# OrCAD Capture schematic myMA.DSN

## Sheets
1 - Cover Page: title: COVER PAGE; rev: 01; note: DE-002031
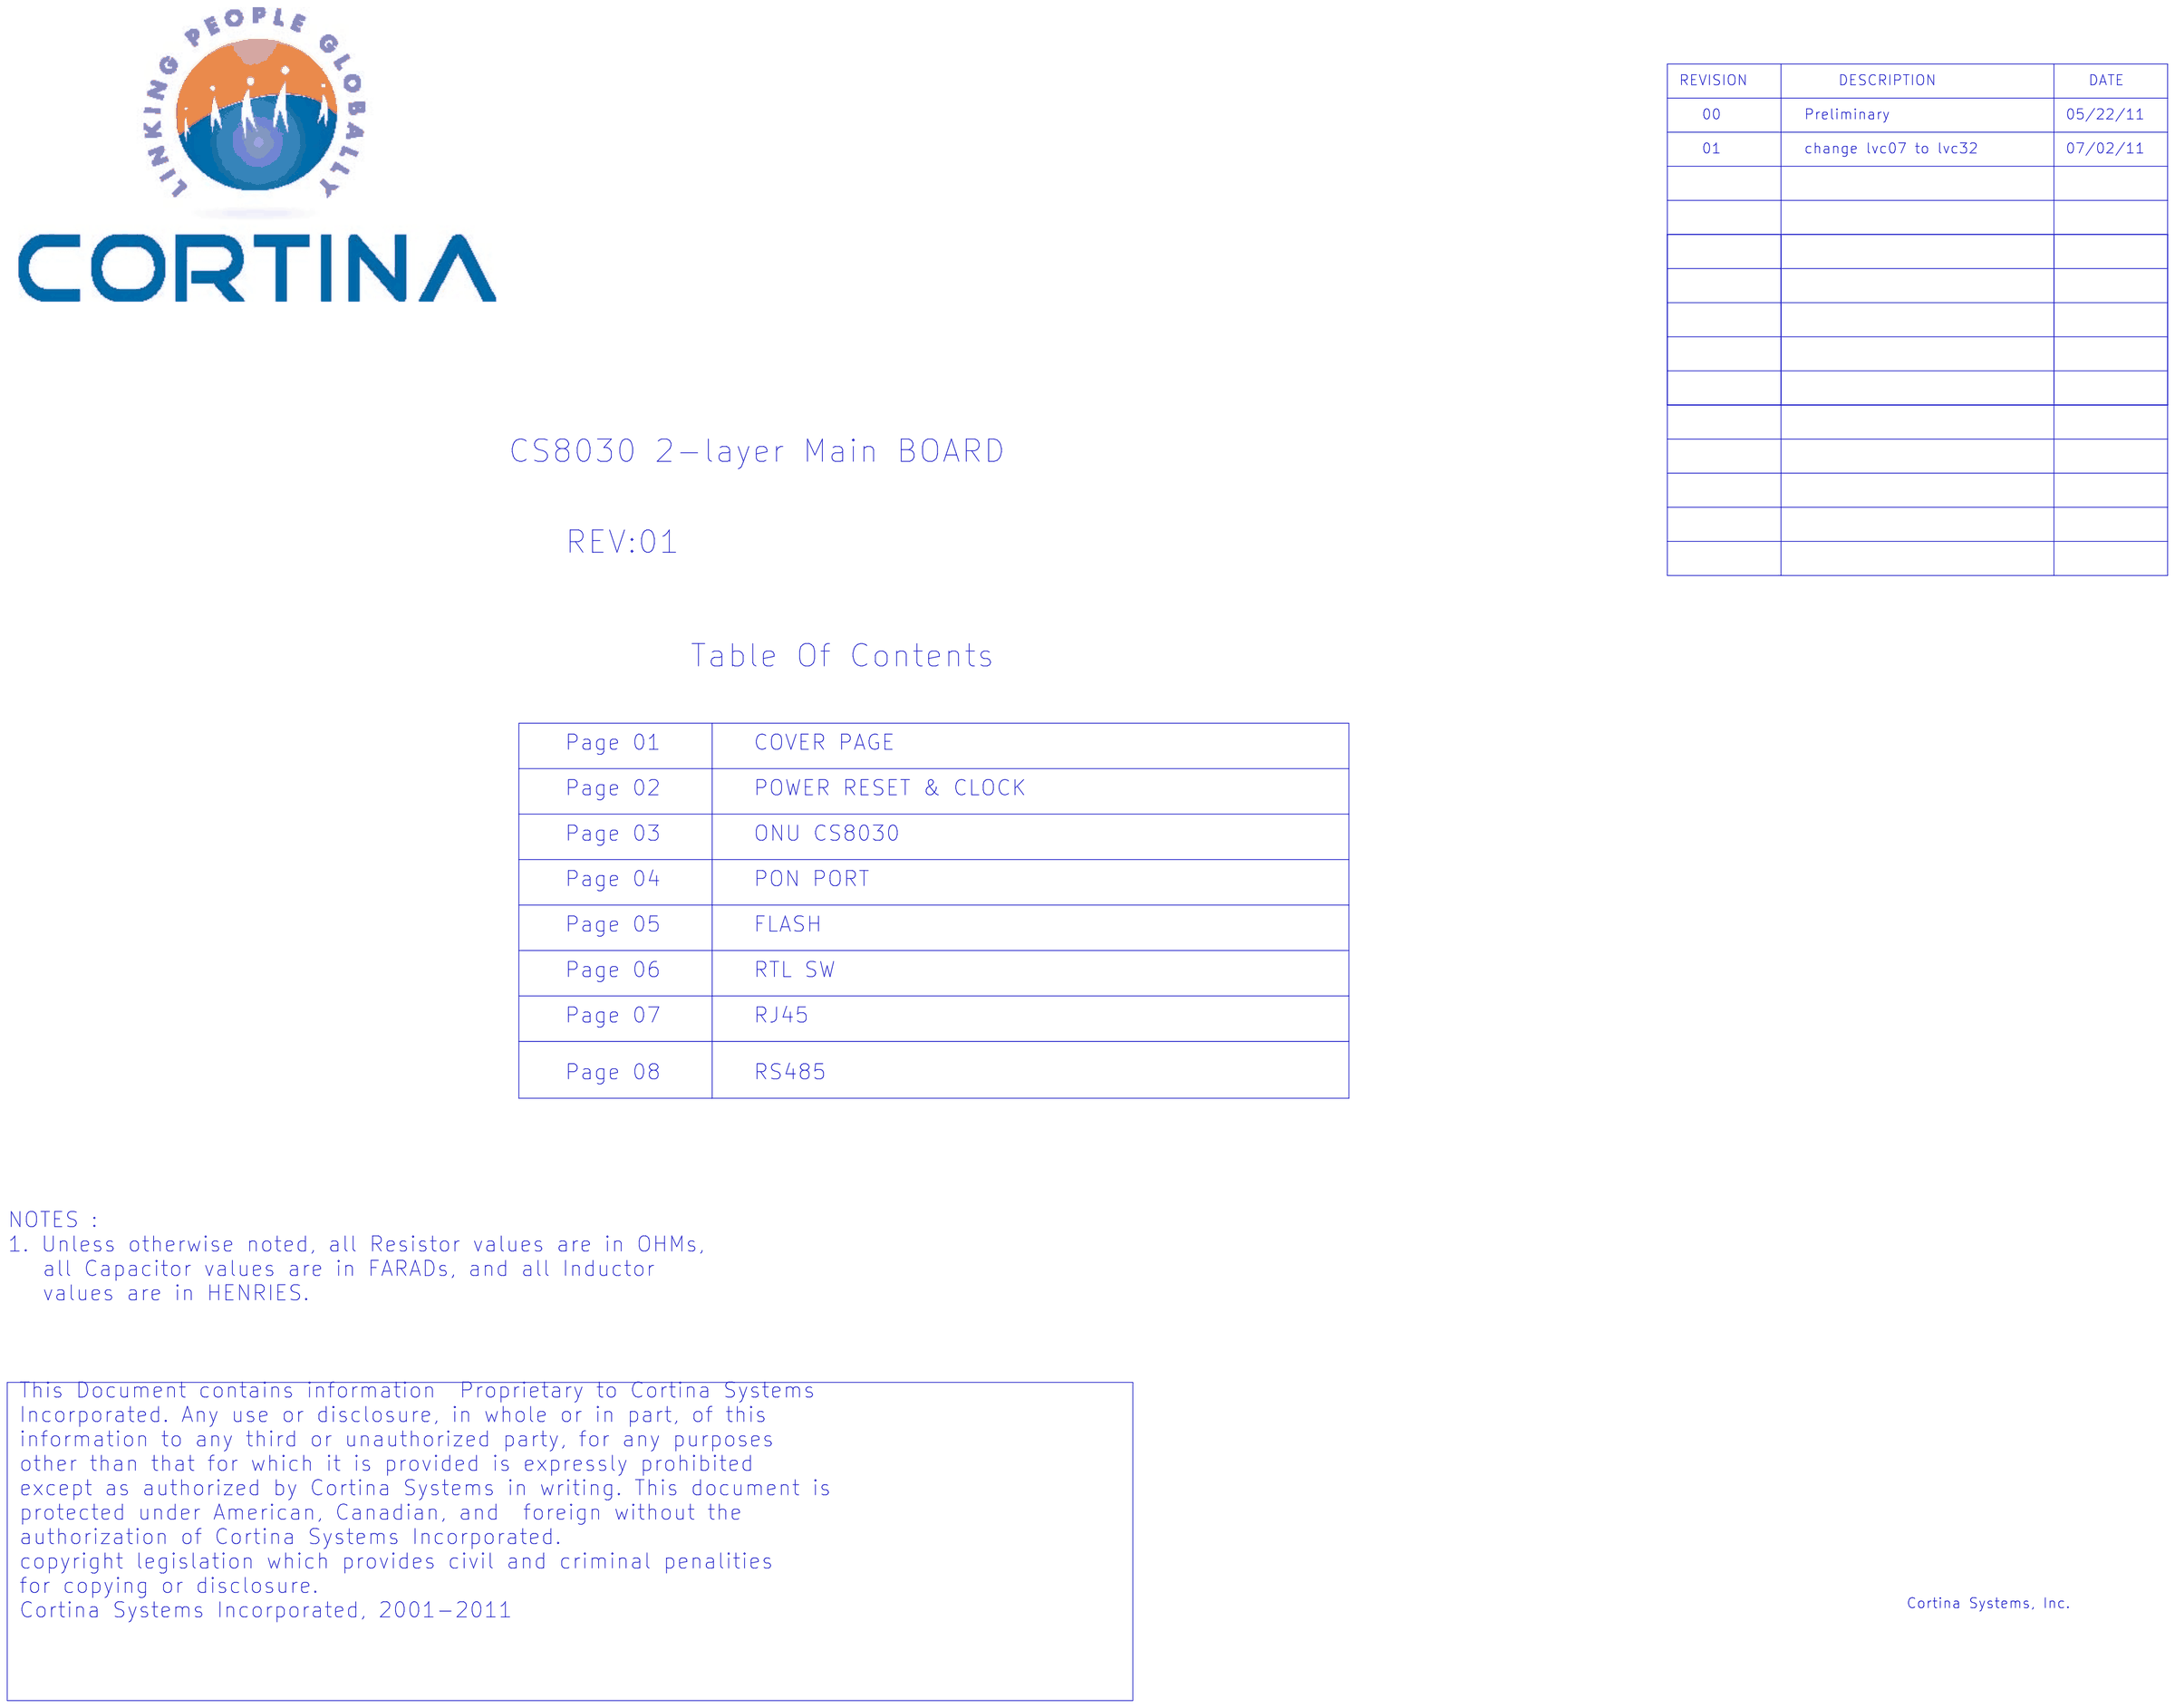
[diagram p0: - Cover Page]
2 - POWER RESET&CLOCK: size C; title: POWER RESET&CLOCK
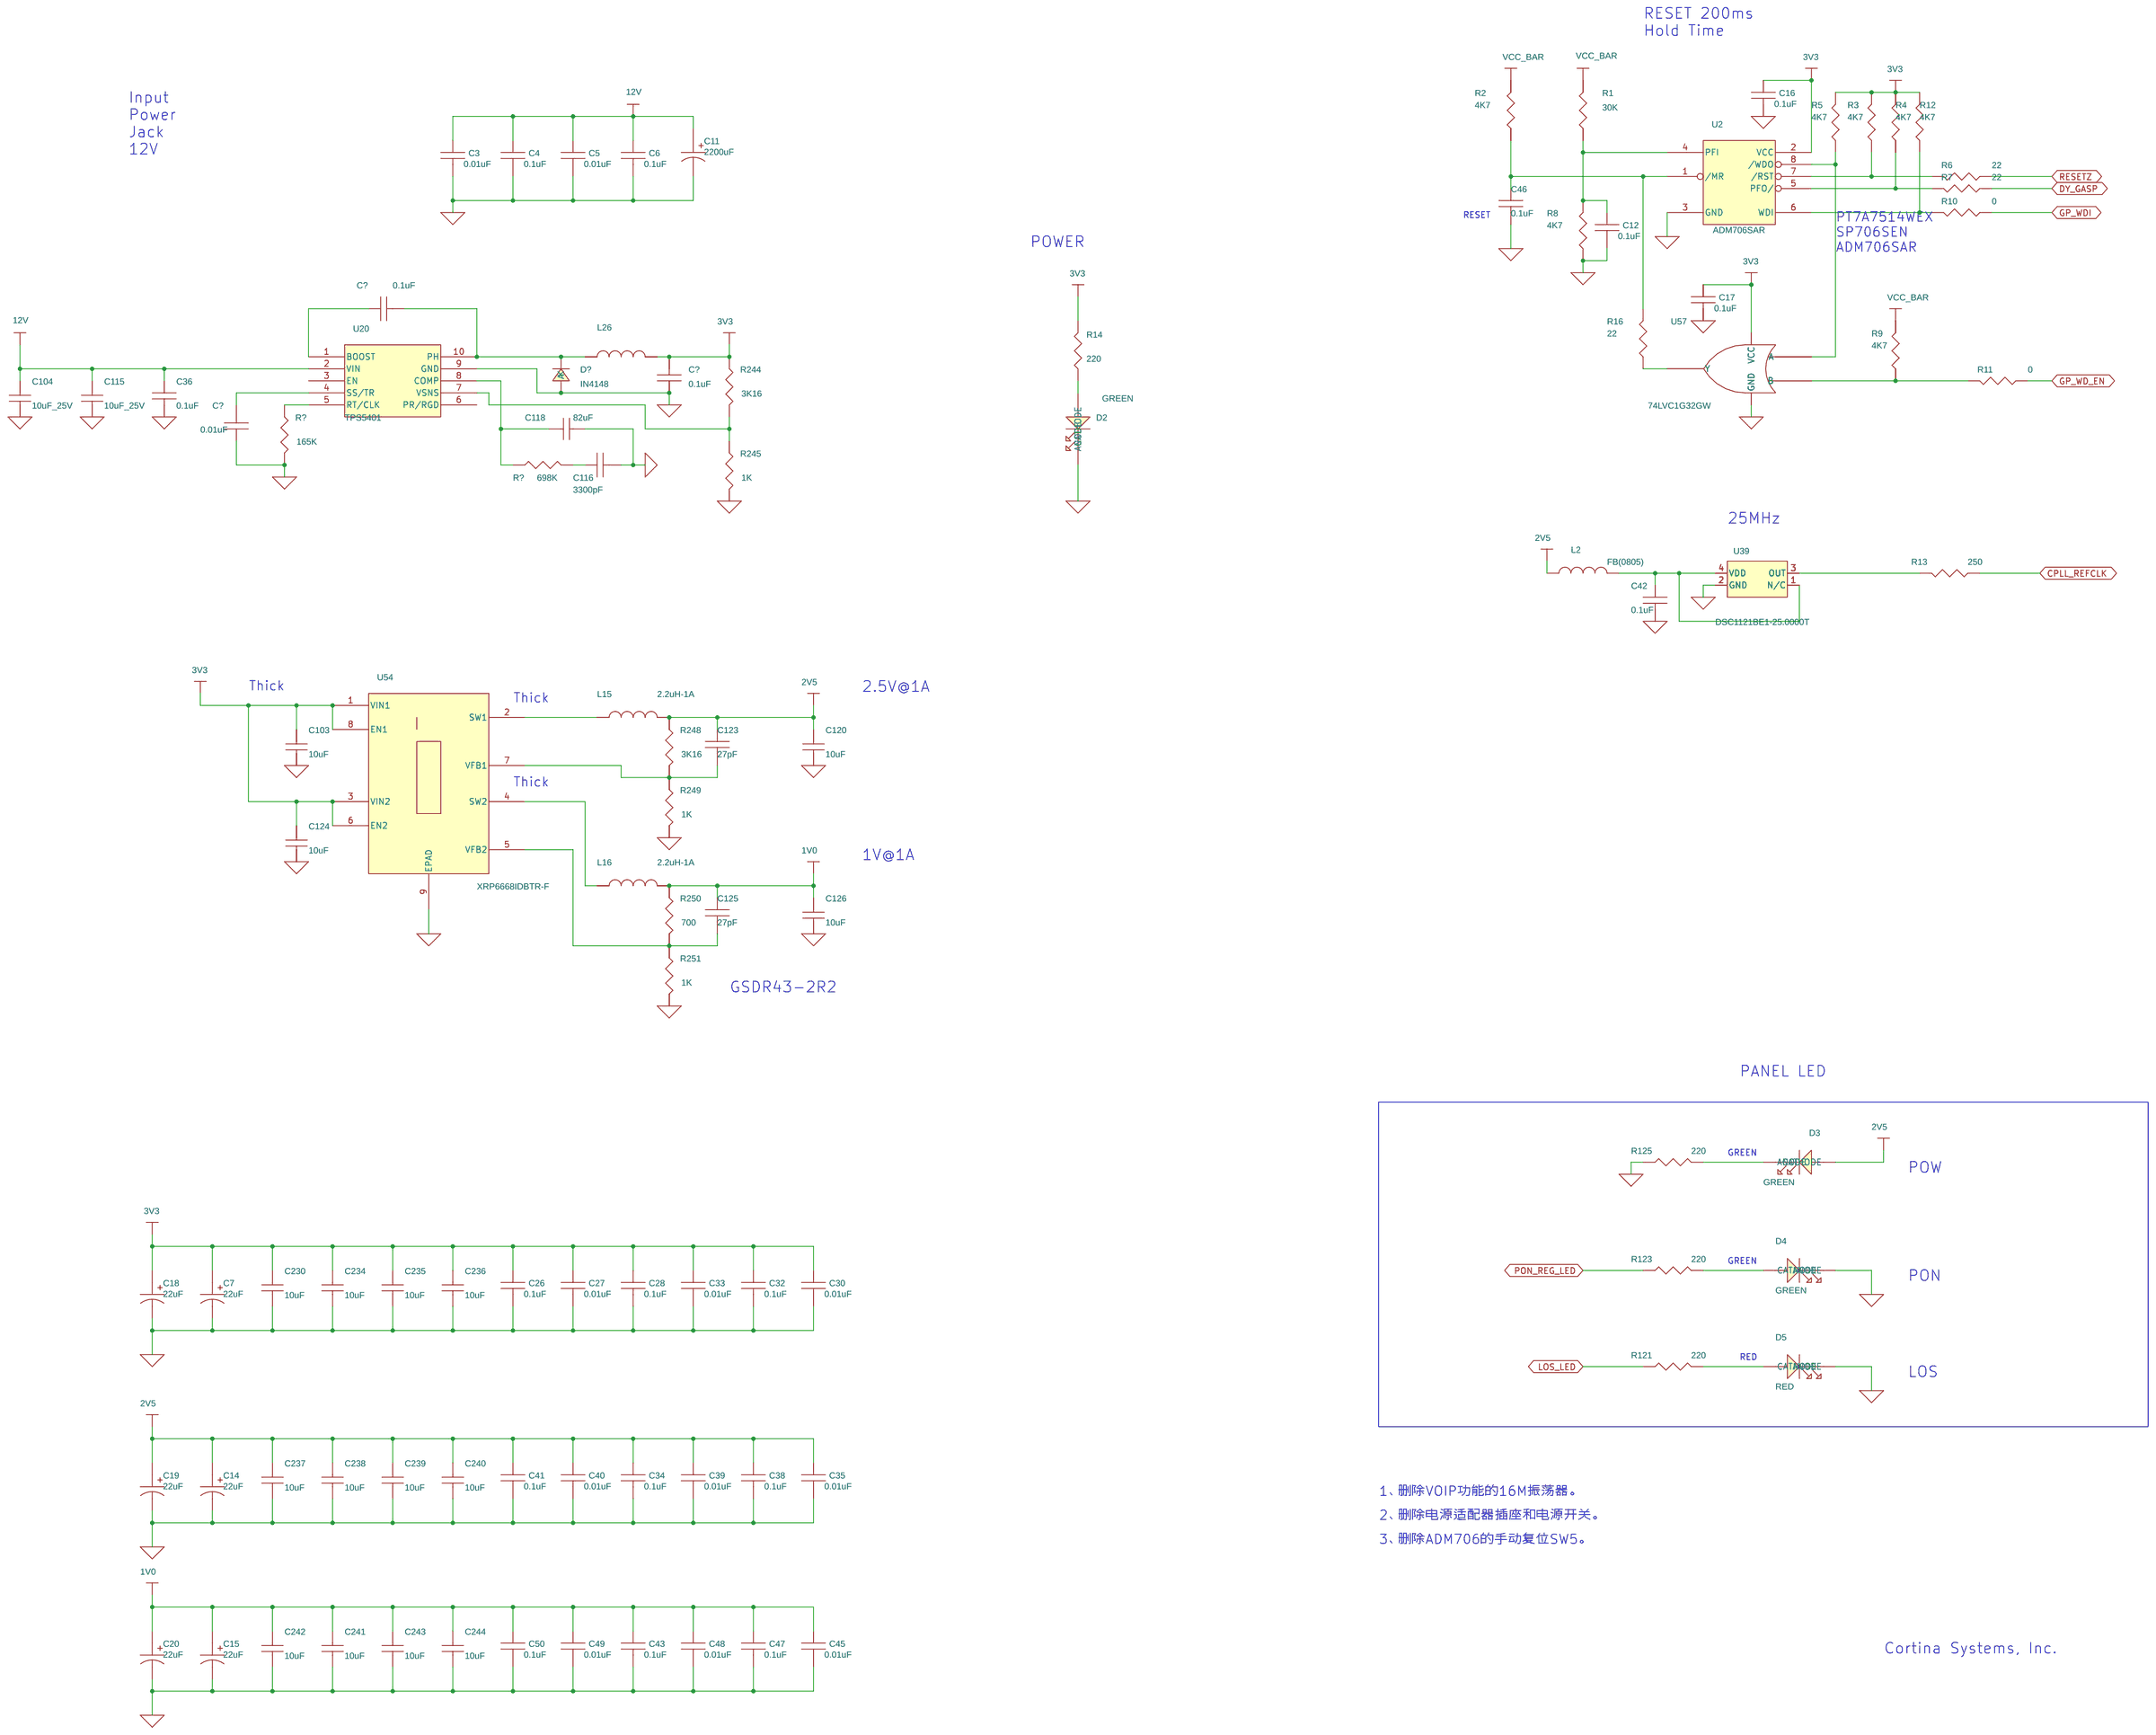
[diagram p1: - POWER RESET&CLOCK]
3 - ONU CS8030: size C; title: CS8030
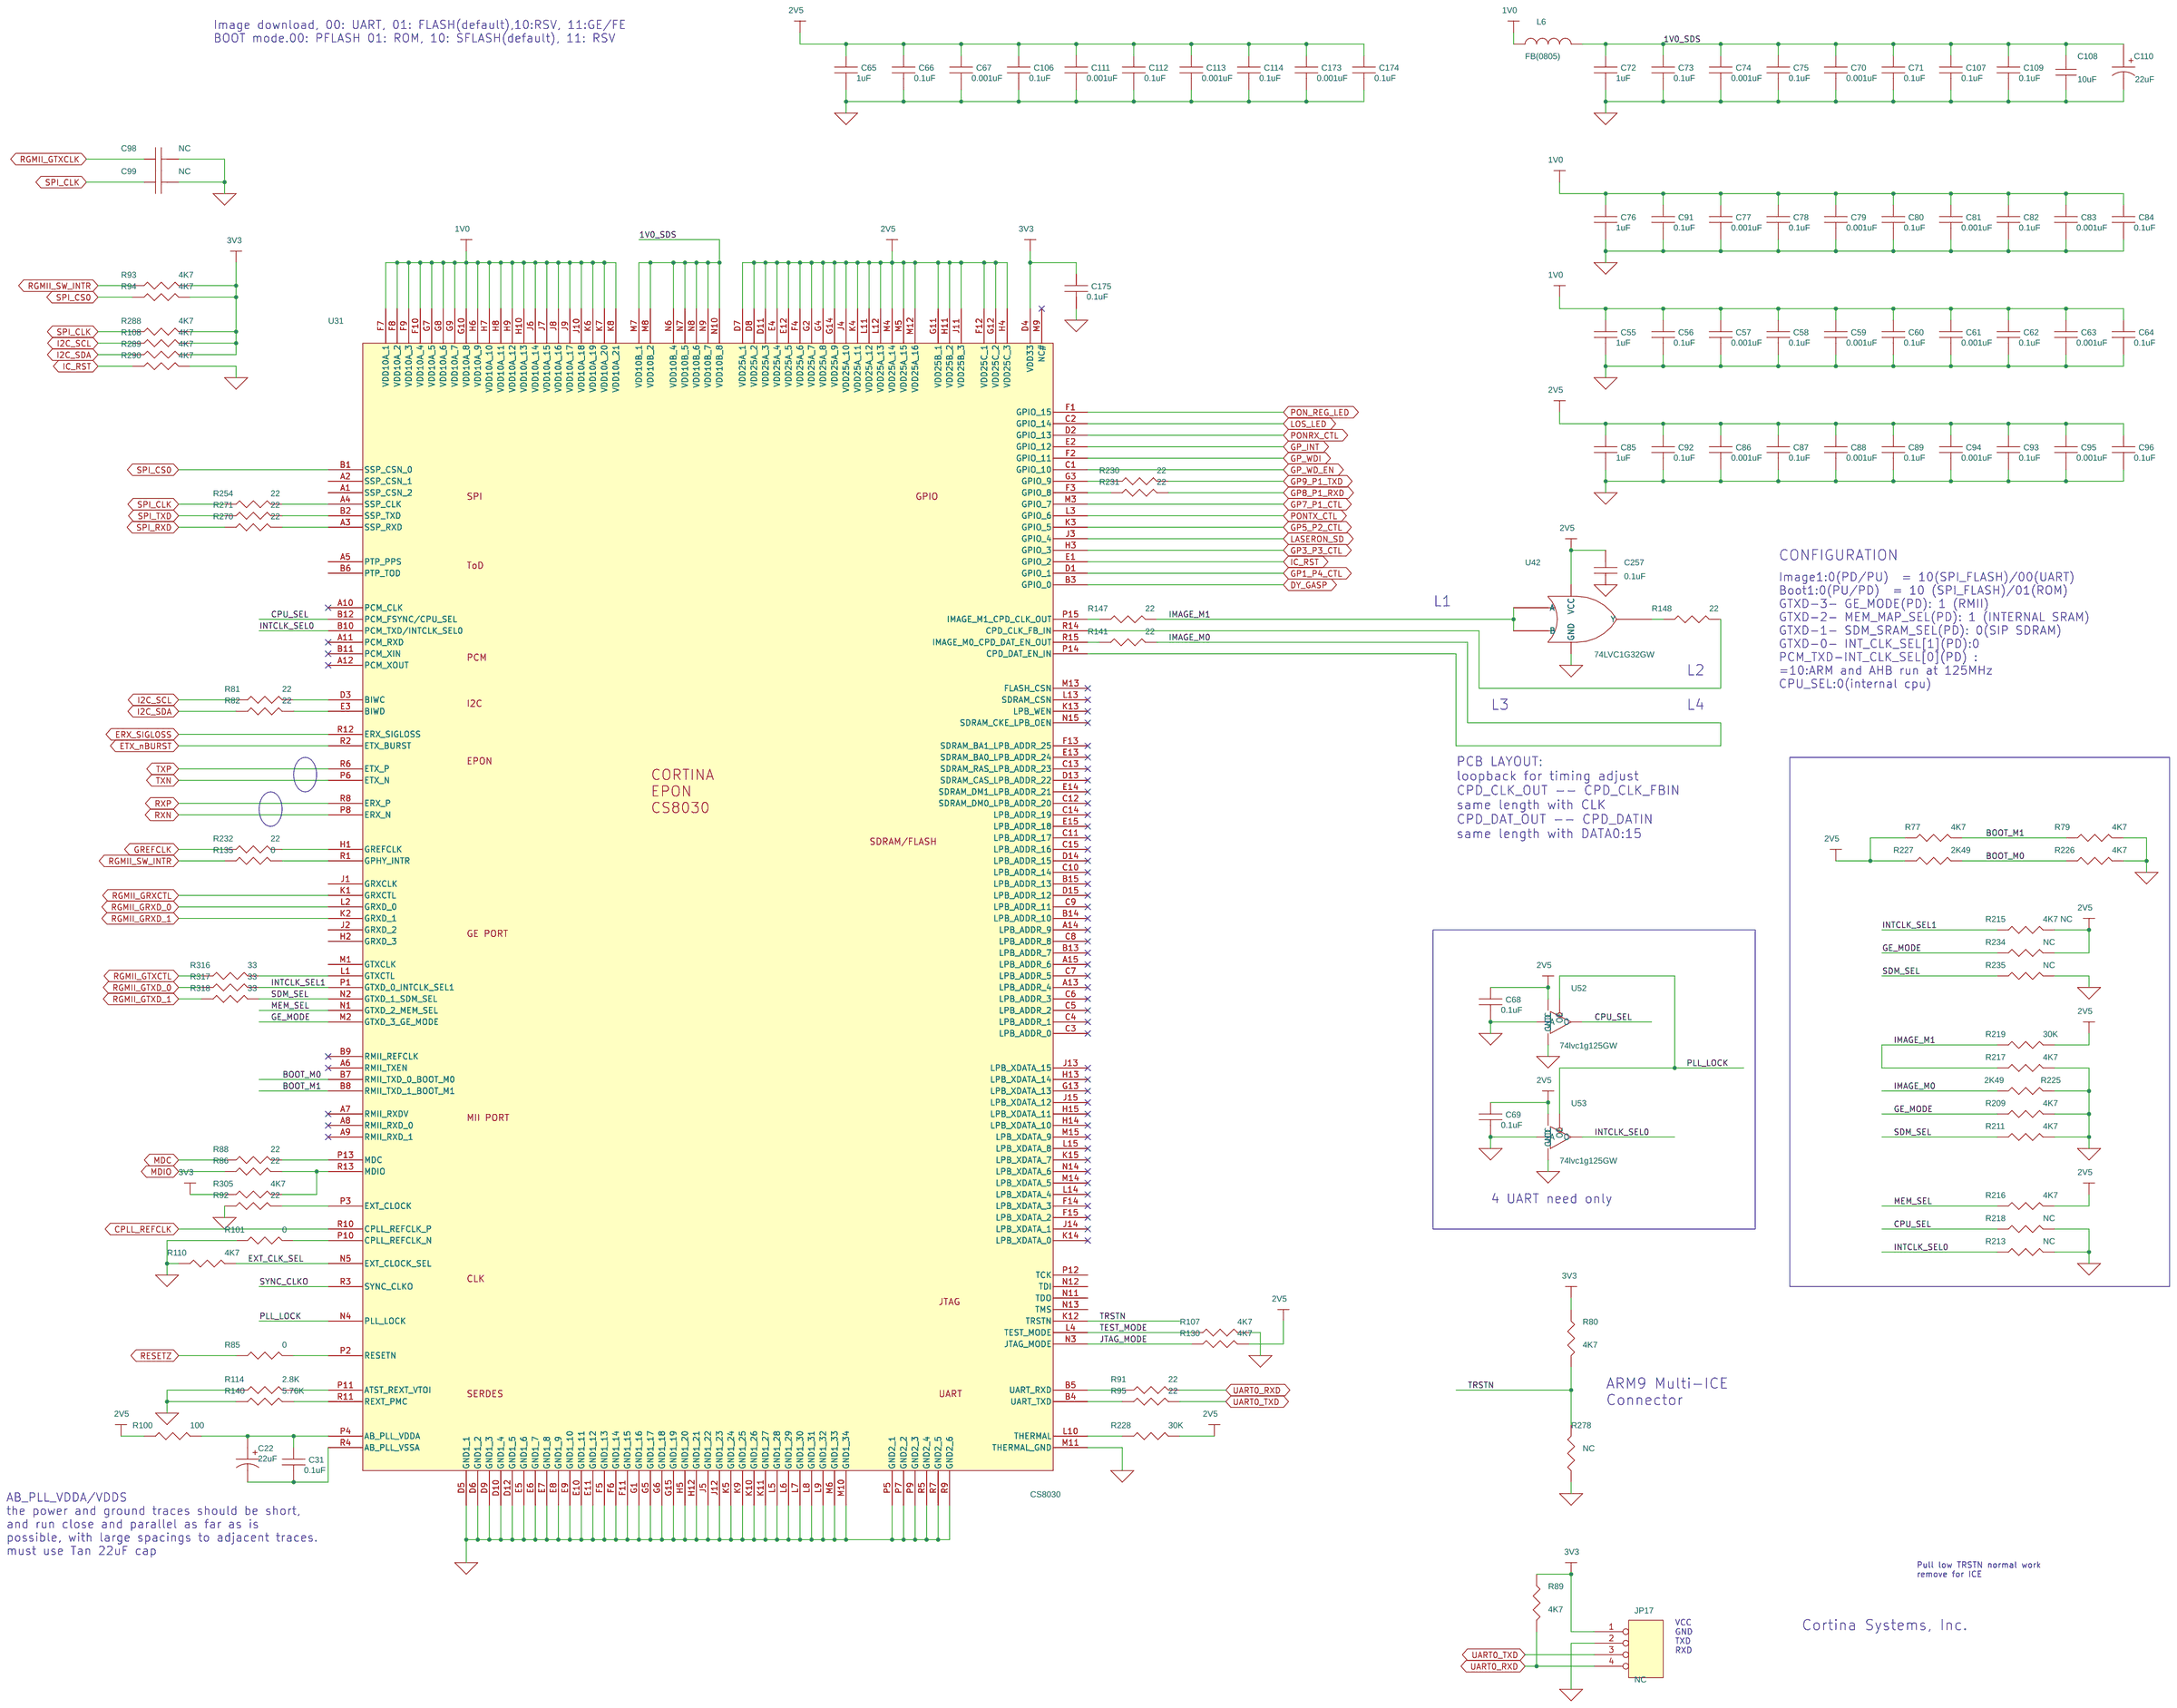
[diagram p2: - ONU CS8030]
4 - PON PORT: size C; title: PON PORT
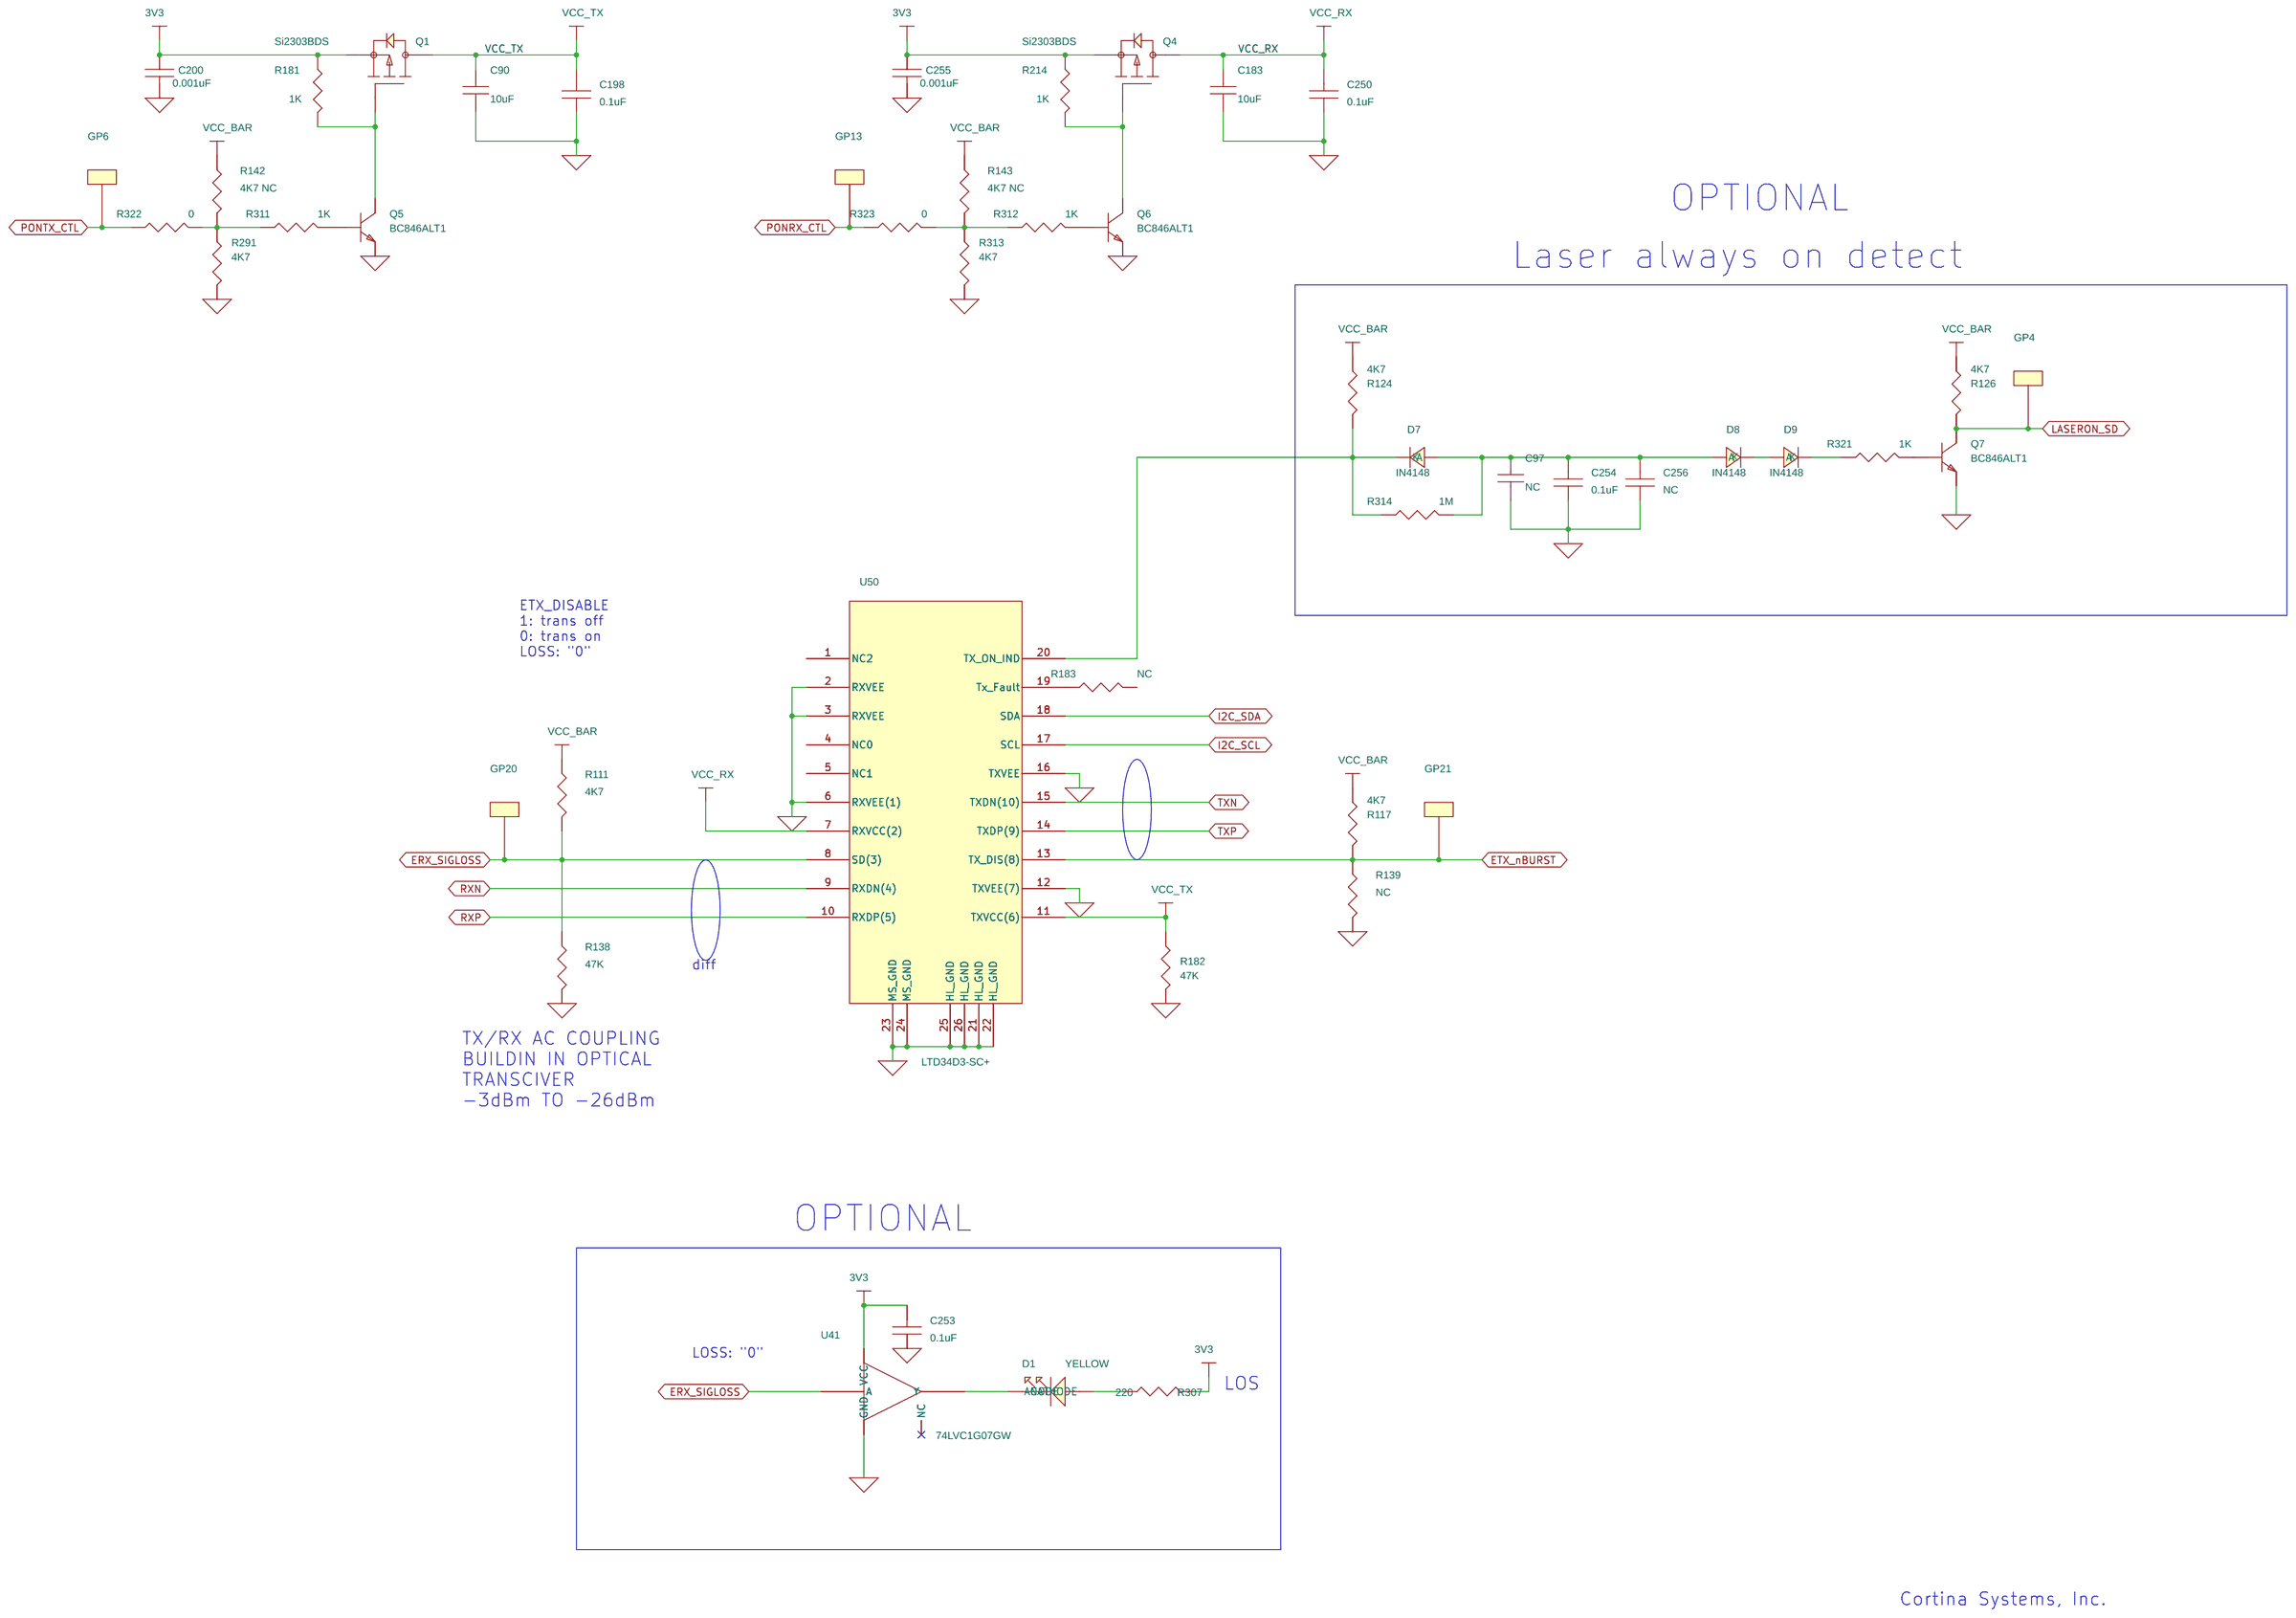
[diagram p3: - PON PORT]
5 - SFLASH_SDRAM: size C; title: FLASH
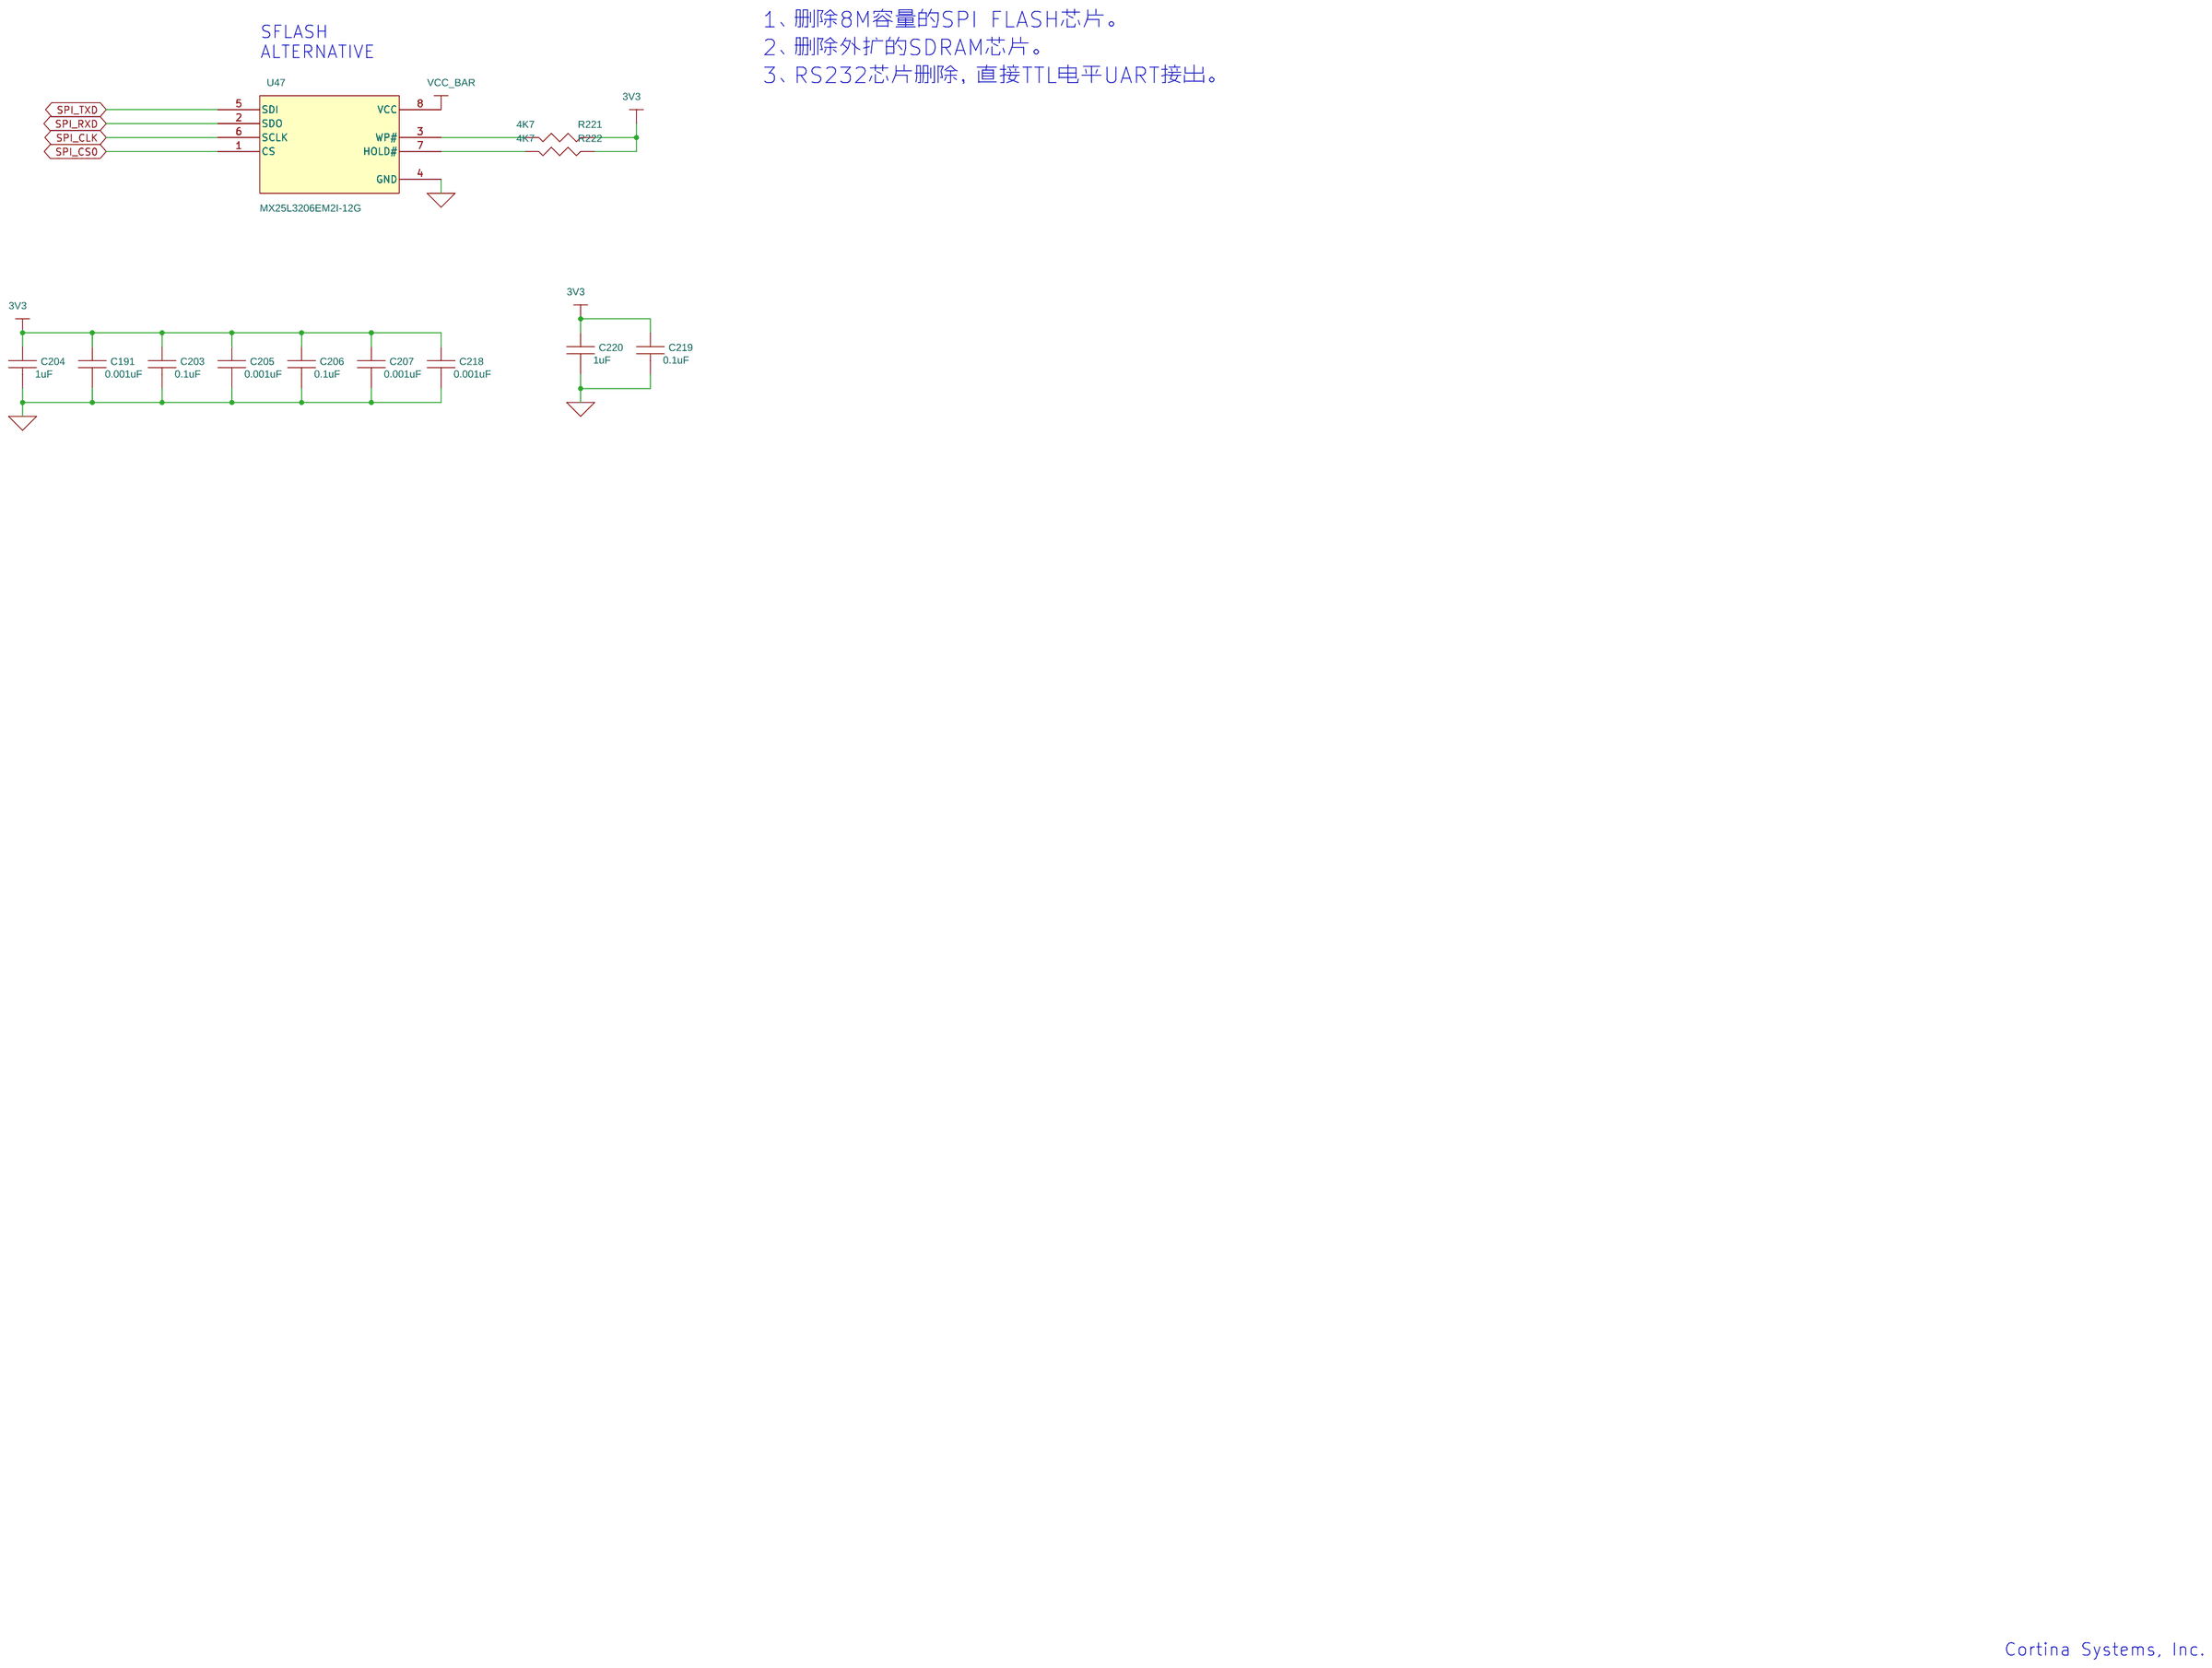
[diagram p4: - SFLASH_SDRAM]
6 - SW_PHY_IF: size C; title: SW PHY
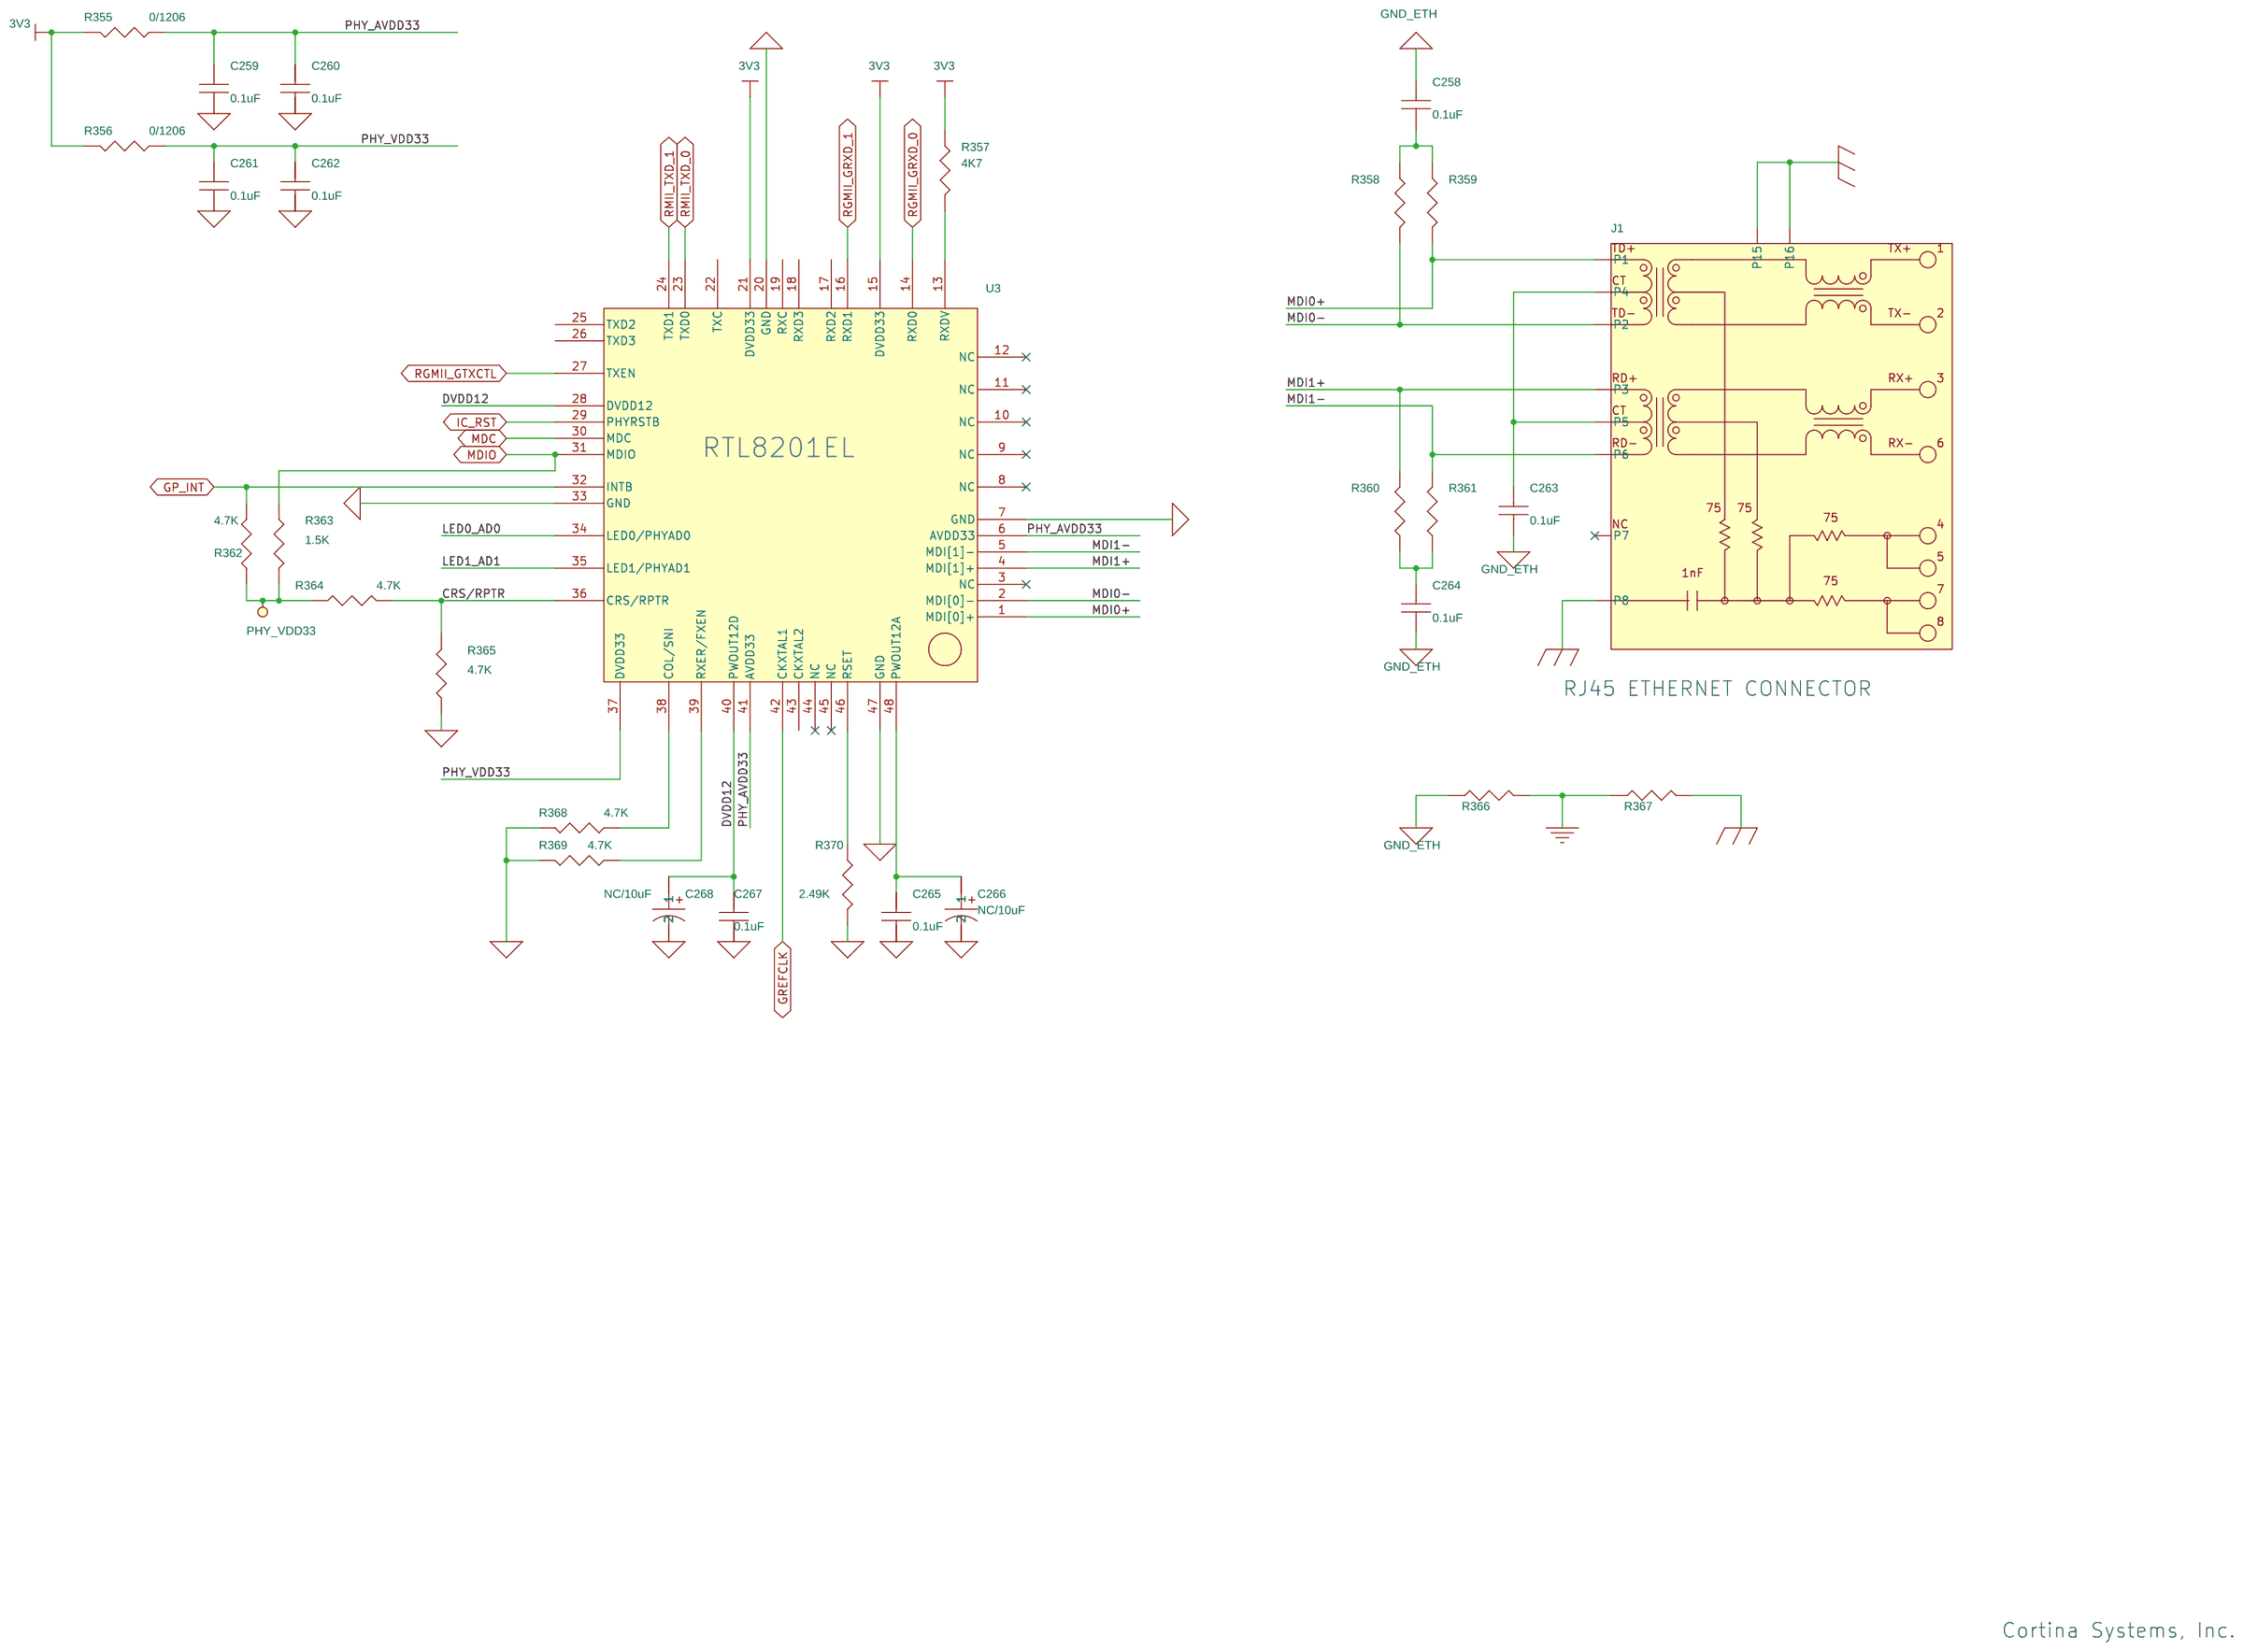
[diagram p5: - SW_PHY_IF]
7 - SLIC_IF: title: SLIC
8 - RS485_RS232: size C; title: RS485
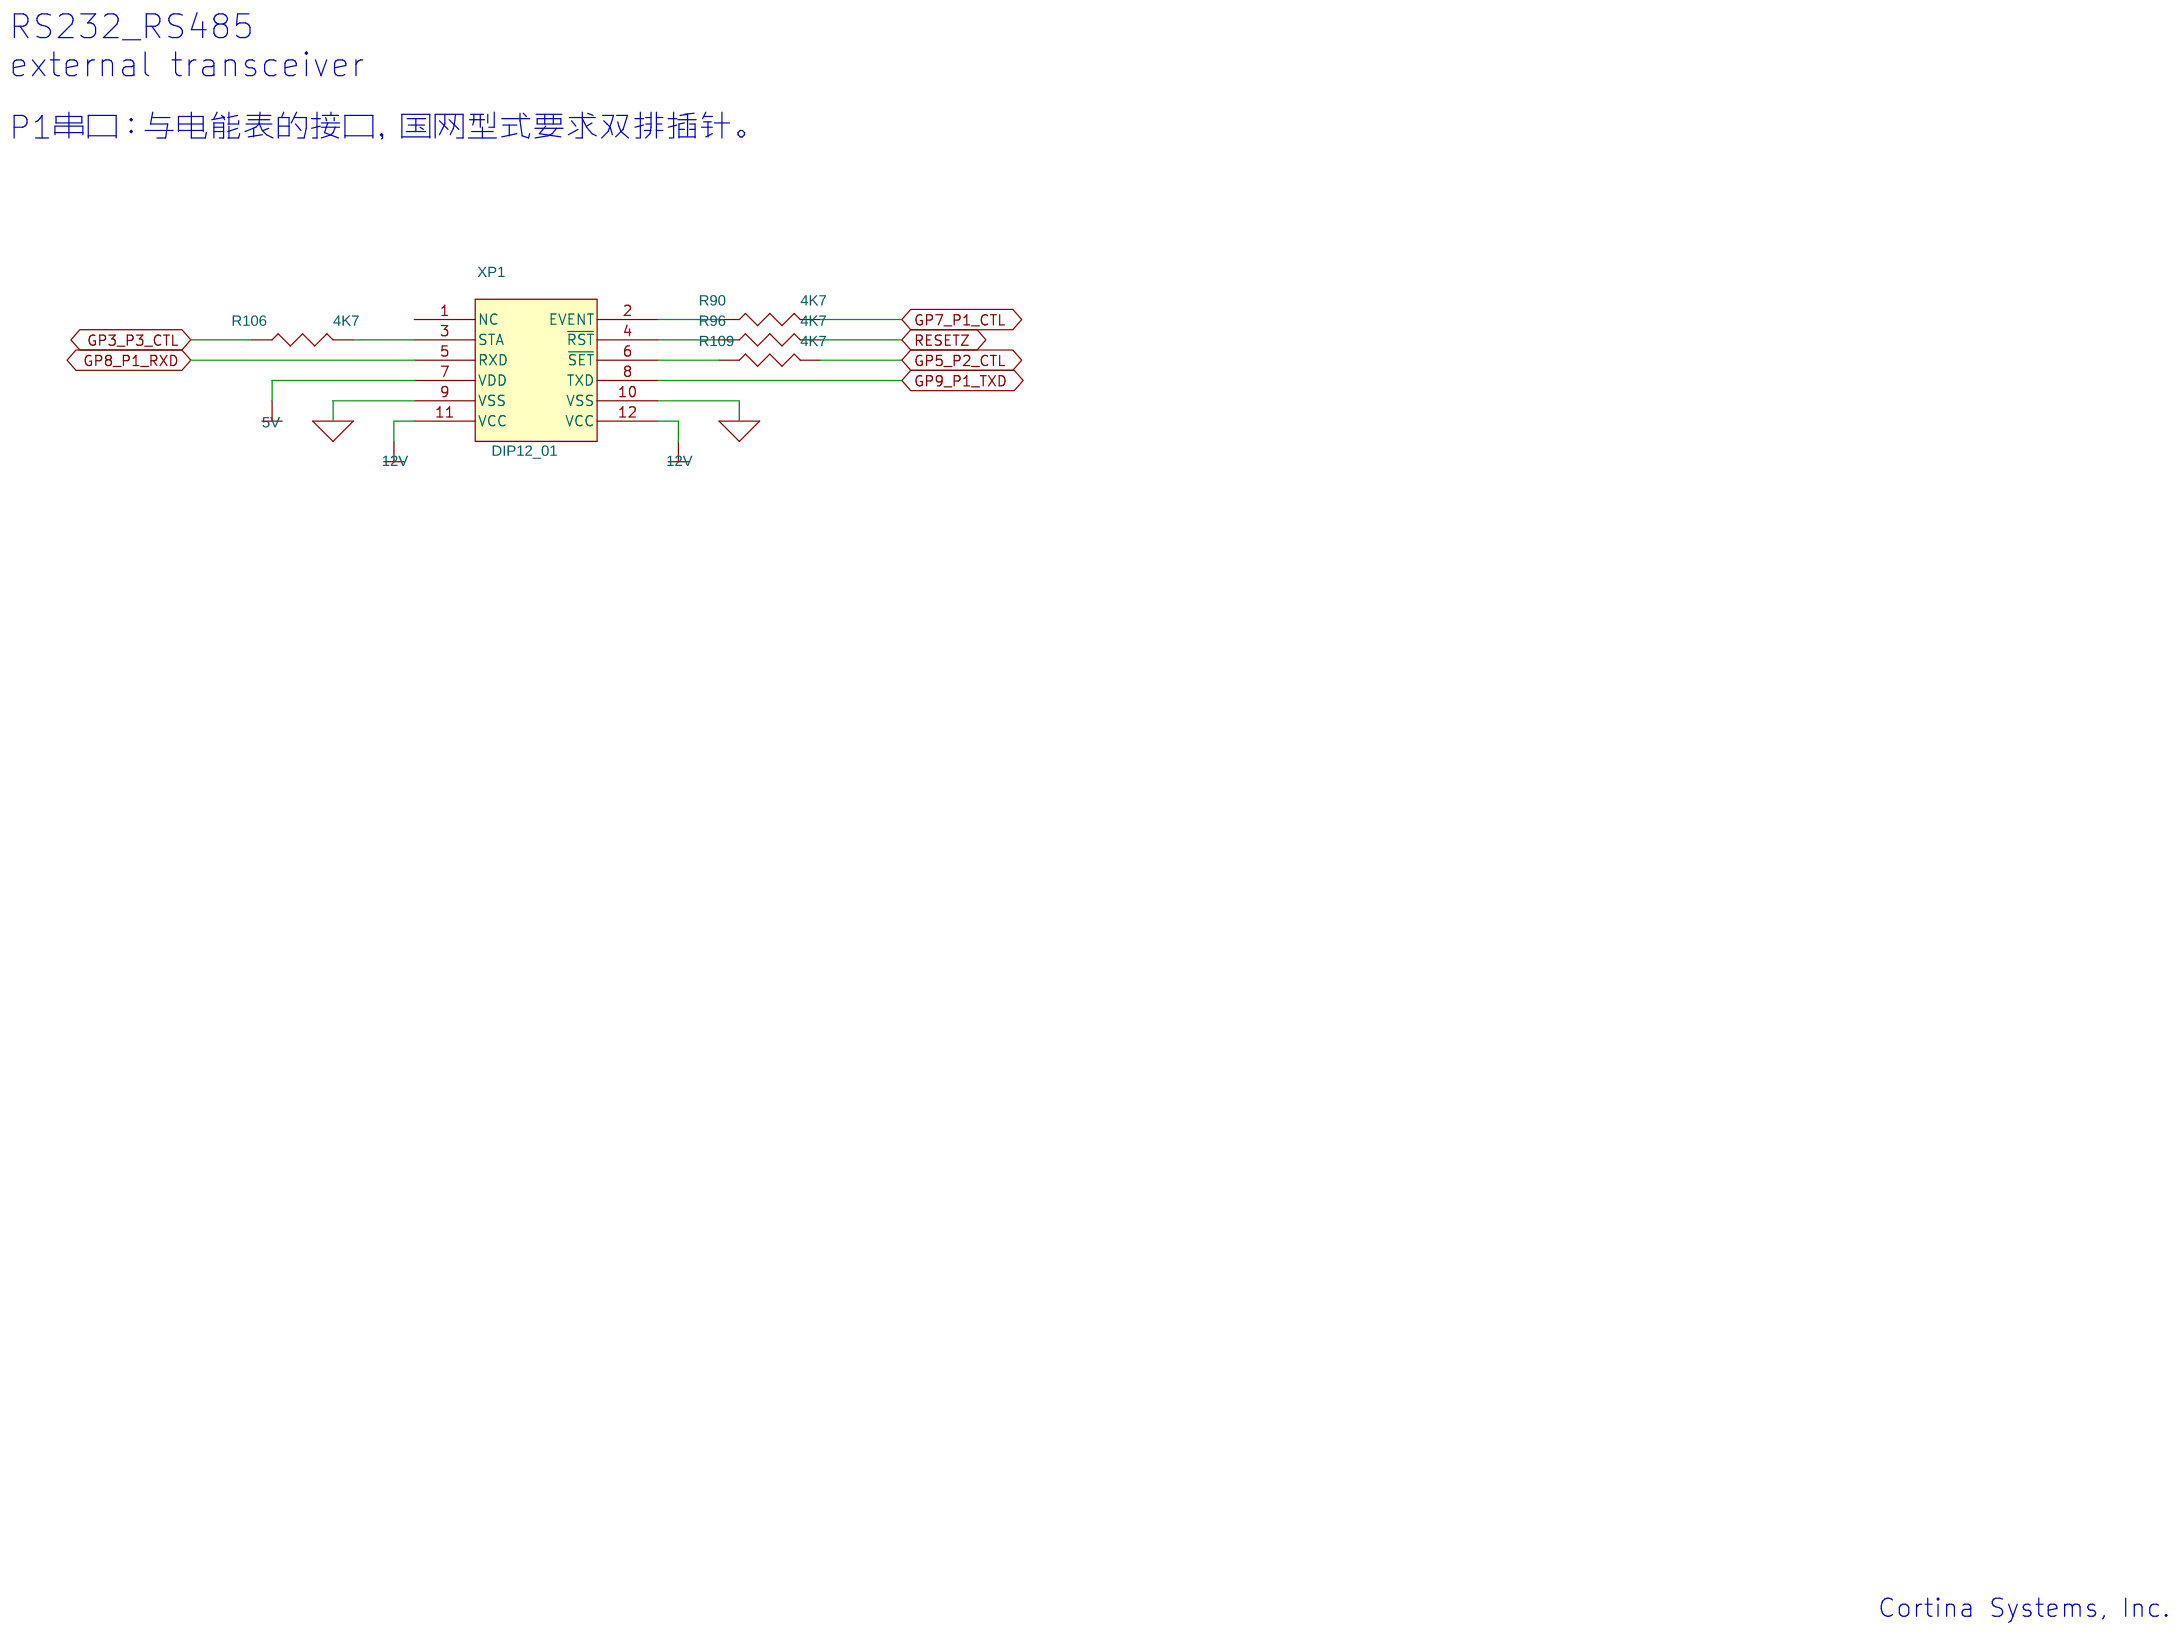
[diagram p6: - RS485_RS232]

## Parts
sheet - ONU CS8030
C22  22uF  [STC3216]
C31  0.1uF  [SC0402]
C55  1uF  [SC0402]
C56  0.1uF  [SC0402]
C57  0.001uF  [SC0402]
C58  0.1uF  [SC0402]
C59  0.001uF  [SC0402]
C60  0.1uF  [SC0402]
C61  0.001uF  [SC0402]
C62  0.1uF  [SC0402]
C63  0.001uF  [SC0402]
C64  0.1uF  [SC0402]
C65  1uF  [SC0402]
C66  0.1uF  [SC0402]
C67  0.001uF  [SC0402]
C68  0.1uF  [SC0402]
C69  0.1uF  [SC0402]
C70  0.001uF  [SC0402]
C71  0.1uF  [SC0402]
C72  1uF  [SC0402]
C73  0.1uF  [SC0402]
C74  0.001uF  [SC0402]
C75  0.1uF  [SC0402]
C76  1uF  [SC0402]
C77  0.001uF  [SC0402]
C78  0.1uF  [SC0402]
C79  0.001uF  [SC0402]
C80  0.1uF  [SC0402]
C81  0.001uF  [SC0402]
C82  0.1uF  [SC0402]
C83  0.001uF  [SC0402]
C84  0.1uF  [SC0402]
C85  1uF  [SC0402]
C86  0.001uF  [SC0402]
C87  0.1uF  [SC0402]
C88  0.001uF  [SC0402]
C89  0.1uF  [SC0402]
C91  0.1uF  [SC0402]
C92  0.1uF  [SC0402]
C93  0.1uF  [SC0402]
C94  0.001uF  [SC0402]
C95  0.001uF  [SC0402]
C96  0.1uF  [SC0402]
C98  NC  [SC0402]
C99  NC  [SC0402]
C106  0.1uF  [SC0402]
C107  0.1uF  [SC0402]
C108  10uF  [SC0805]
C109  0.1uF  [SC0402]
C110  22uF  [STC3216]
C111  0.001uF  [SC0402]
C112  0.1uF  [SC0402]
C113  0.001uF  [SC0402]
C114  0.1uF  [SC0402]
C173  0.001uF  [SC0402]
C174  0.1uF  [SC0402]
C175  0.1uF  [SC0402]
C257  0.1uF  [SC0402]
JP17  NC  [HEADER4-100]
L6  FB(0805)  [SL0805]
R77  4K7  [SR0402]
R79  4K7  [SR0402]
R80  4K7  [SR0402]
R81  22  [SR0402]
R82  22  [SR0402]
R85  0  [SR0402]
R86  22  [SR0402]
R88  22  [SR0402]
R89  4K7  [SR0402]
R91  22  [SR0402]
R92  22  [SR0402]
R93  4K7  [SR0402]
R94  4K7  [SR0402]
R95  22  [SR0402]
R100  100  [SR0603]
R101  0  [SR0402]
R107  4K7  [SR0402]
R108  4K7  [SR0402]
R110  4K7  [SR0402]
R114  2.8K  [SR0402]
R130  4K7  [SR0402]
R135  0  [SR0402]
R140  5.76K  [SR0402]
R141  22  [SR0402]
R147  22  [SR0402]
R148  22  [SR0402]
R209  4K7  [SR0402]
R211  4K7  [SR0402]
R213  NC  [SR0402]
R215  4K7 NC  [SR0402]
R216  4K7  [SR0402]
R217  4K7  [SR0402]
R218  NC  [SR0402]
R219  30K  [SR0402]
R225  2K49  [SR0402]
R226  4K7  [SR0402]
R227  2K49  [SR0402]
R228  30K  [SR0402]
R230  22  [SR0402]
R231  22  [SR0402]
R232  22  [SR0402]
R234  NC  [SR0402]
R235  NC  [SR0402]
R254  22  [SR0402]
R270  22  [SR0402]
R271  22  [SR0402]
R278  NC  [SR0402]
R288  4K7  [SR0402]
R289  4K7  [SR0402]
R290  4K7  [SR0402]
R305  4K7  [SR0402]
R316  33  [SR0402]
R317  33  [SR0402]
R318  33  [SR0402]
U31  CS8030  [BGA_08_225]
U42  74LVC1G32GW  [SOT353]
U52  74lvc1g125GW  [SOT353]
U53  74lvc1g125GW  [SOT353]
sheet - PON PORT
C90  10uF  [SC0805]
C97  NC  [SC0805]
C183  10uF  [SC0805]
C198  0.1uF  [SC0402]
C200  0.001uF  [SC0402]
C250  0.1uF  [SC0402]
C253  0.1uF  [SC0402]
C254  0.1uF  [SC0402]
C255  0.001uF  [SC0402]
C256  NC  [SC0402]
D1  YELLOW  [0805D]
D7  DIODE  [SMA_B]
D8  DIODE  [SMA_B]
D9  DIODE  [SMA_B]
GP4  -  [TP]
GP6  -  [TP]
GP13  -  [TP]
GP20  -  [TP]
GP21  -  [TP]
Q1  Si2303BDS  [SOT23]
Q4  Si2303BDS  [SOT23]
Q5  BC846ALT1  [SOT23]
Q6  BC846ALT1  [SOT23]
Q7  BC846ALT1  [SOT23]
R111  4K7  [SR0402]
R117  4K7  [SR0402]
R124  4K7  [SR0402]
R126  4K7  [SR0402]
R138  47K  [SR0402]
R139  NC  [SR0402]
R142  4K7 NC  [SR0402]
R143  4K7 NC  [SR0402]
R181  1K  [SR0402]
R182  47K  [SR0402]
R183  NC  [SR0402]
R214  1K  [SR0402]
R291  4K7  [SR0402]
R307  220  [SR0402]
R311  1K  [SR0402]
R312  1K  [SR0402]
R313  4K7  [SR0402]
R314  1M  [SR0402]
R321  1K  [SR0402]
R322  0  [SR0402]
R323  0  [SR0402]
U41  74LVC1G07GW  [SOT353]
U50  LTD34D3-SC+  [SFF2X10-rs485]
sheet - POWER RESET&CLOCK
C3  0.01uF  [SC0402]
C4  0.1uF  [SC0402]
C5  0.01uF  [SC0402]
C6  0.1uF  [SC0402]
C7  22uF  [STC3216]
C11  2200uF  [CAP-235-470]
C12  0.1uF  [SC0402]
C14  22uF  [STC3216]
C15  22uF  [STC3216]
C16  0.1uF  [SC0402]
C17  0.1uF  [SC0402]
C18  22uF  [STC3216]
C19  22uF  [STC3216]
C20  22uF  [STC3216]
C26  0.1uF  [SC0402]
C27  0.01uF  [SC0402]
C28  0.1uF  [SC0402]
C30  0.01uF  [SC0402]
C32  0.1uF  [SC0402]
C33  0.01uF  [SC0402]
C34  0.1uF  [SC0402]
C35  0.01uF  [SC0402]
C36  0.1uF  [SC0402]
C38  0.1uF  [SC0402]
C39  0.01uF  [SC0402]
C40  0.01uF  [SC0402]
C41  0.1uF  [SC0402]
C42  0.1uF  [SC0402]
C43  0.1uF  [SC0402]
C45  0.01uF  [SC0402]
C46  0.1uF  [SC0402]
C47  0.1uF  [SC0402]
C48  0.01uF  [SC0402]
C49  0.01uF  [SC0402]
C50  0.1uF  [SC0402]
C103  10uF  [SC0805]
C104  10uF_25V  [SC1206]
C115  10uF_25V  [SC1206]
C116  3300pF  [SC0402]
C118  82uF  [SC1206]
C120  10uF  [SC0805]
C123  27pF  [SC0402]
C124  10uF  [SC0805]
C125  27pF  [SC0402]
C126  10uF  [SC0805]
C230  10uF  [SC0805]
C234  10uF  [SC0805]
C235  10uF  [SC0805]
C236  10uF  [SC0805]
C237  10uF  [SC0805]
C238  10uF  [SC0805]
C239  10uF  [SC0805]
C240  10uF  [SC0805]
C241  10uF  [SC0805]
C242  10uF  [SC0805]
C243  10uF  [SC0805]
C244  10uF  [SC0805]
C?#1  0.1uF  [SC0402]
C?#2  0.1uF  [SC0402]
C?#3  0.01uF  [SC0402]
D2  GREEN  [0805D]
D3  GREEN  [0805D]
D4  GREEN  [0805D]
D5  RED  [0805D]
D?#4  DIODE  [SMA_B]
L2  FB(0805)  [SL0805]
L15  2.2uH-1A  [L_GSDR43]
L16  2.2uH-1A  [L_GSDR43]
L26  NR6020T3R3N  [NR6020T3R3N]
R1  30K  [SR0402]
R2  4K7  [SR0402]
R3  4K7  [SR0402]
R4  4K7  [SR0402]
R5  4K7  [SR0402]
R6  22  [SR0402]
R7  22  [SR0402]
R8  4K7  [SR0402]
R9  4K7  [SR0402]
R10  0  [SR0402]
R11  0  [SR0402]
R12  4K7  [SR0402]
R13  250  [SR0402]
R14  220  [SR0402]
R16  22  [SR0402]
R121  220  [SR0402]
R123  220  [SR0402]
R125  220  [SR0402]
R244  3K16  [SR0402]
R245  1K  [SR0402]
R248  3K16  [SR0402]
R249  1K  [SR0402]
R250  700  [SR0402]
R251  1K  [SR0402]
R?#5  165K  [SR0402]
R?#6  698K  [SR0402]
U2  ADM706SAR  [SOIC8A_1-27]
U20  TPS5401
U39  DSC1121BE1-25.0000T  [OSC_5X32]
U54  XRP6668IDBTR-F  [XRP6668]
U57  74LVC1G32GW  [SOT353]
sheet - RS485_RS232
R90  4K7  [SR0402]
R96  4K7  [SR0402]
R106  4K7  [SR0402]
R109  4K7  [SR0402]
XP1  DIP12_01
sheet - SFLASH_SDRAM
C191  0.001uF  [SC0402]
C203  0.1uF  [SC0402]
C204  1uF  [SC0402]
C205  0.001uF  [SC0402]
C206  0.1uF  [SC0402]
C207  0.001uF  [SC0402]
C218  0.001uF  [SC0402]
C219  0.1uF  [SC0402]
C220  1uF  [SC0402]
R221  4K7  [SR0402]
R222  4K7  [SR0402]
U47  MX25L3206EM2I-12G  [SOIC8_200MIL]
sheet - SW_PHY_IF
C258  0.1uF
C259  0.1uF
C260  0.1uF
C261  0.1uF
C262  0.1uF
C263  0.1uF
C264  0.1uF
C265  0.1uF
C266  NC/10uF
C267  0.1uF
C268  NC/10uF
J1  J00-0061 PULSE  [RJ45_PULSE]
R355  0/1206
R356  0/1206
R357  4K7  [SR0402]
R358  49R9-0805  [R0805]
R359  49R9-0805  [R0805]
R360  49R9-0805  [R0805]
R361  49R9-0805  [R0805]
R362  4.7K
R363  1.5K
R364  4.7K
R365  4.7K
R366  0R-0603  [R0603]
R367  0R-0603  [R0603]
R368  4.7K
R369  4.7K
R370  2.49K
U3  RTL8201EL

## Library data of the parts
C7 C14 C15 C18-C20 C22 C110 = CAP_1: CAP, TANT, CASE_C, 100, 10%, 6.3V; Mfr Name: SANYO; Mfr P/N: 6TPB100M
C4 C6 C16 C17 C26 C28 C31 C32 C34 C36 C38 C41-C43 C46 C47 C50 C56 C58 C60 C62 C64 C66 C68 C69 C71 C73 C75 C78 C80 C82 C84 C87 C89 C91-C93 C96 C98 C99 C106 C107 C109 C112 C114 C174 C175 C203 C204 C206 C220 C?#1-C?#3 = C_1224: CAP, CER, SMT,0805, 0.1uF/50V, 10%; ALT_SYMBOLS: (SC0402,SC0402_BGA;B:SC0402,SC0402_BGA); Mfr Name: NOVACAP; Mfr P/N: 0805B104K500NX; Vendor Name: Garrett Electronics Corp; Vendor P/N: 0805B104K500NX
C3 C5 C12 C27 C30 C33 C35 C39 C40 C45 C48 C49 C55 C57 C59 C61 C63 C65 C67 C70 C72 C74 C76 C77 C79 C81 C83 C85 C86 C88 C94 C95 C111 C113 C173 C191 C200 C205 C207 C218 C219 C255 = C_1224: CAP, CER, SMT,0805, 100pF/100V, 5%; ALT_SYMBOLS: (SC0402,SC0402_BGA;B:SC0402,SC0402_BGA); Mfr Name: NOVACAP; Mfr P/N: 0805N101J101N; Vendor Name: Garrett Electronics Corp; Vendor P/N: 0805N101J101N
C90 C97 C103 C104 C108 C115 C118 C120 C124 C126 C183 C230 C234-C244 = CAP_NP
C198 C250 C253 C254 C256 C257 = C_1224: ALT_SYMBOLS: (SC0402,SC0402_BGA;B:SC0402,SC0402_BGA); Agile number: CXX0367700; MFG: Panasonic - ECG; MFG_P/N: ECJ-1VB1C104K
JP17 = 4_HEADER_0
L2 L6 = L
R6 R7 R10 R11 R13 R77 R79-R82 R85 R86 R88-R92 R95 R96 R100 R101 R106 R109 R121 R123 R125 R135 R141 R147 R148 R254 R270 R271 R278 R307 R316-R318 = R_1224
R1 R93 R94 R107 R108 R110 R114 R130 R140 R209 R211 R213 R215-R219 R225-R228 R230-R232 R234 R235 R288-R291 R305 R313 = R_1224: Agile number: RJX0455500; MFG: Panasonic - ECG; MFG_P/N: ERJ-3EKF1500V
U31 = lynxd_CS8030
U42 U57 = 74LVC1G32
U52 U53 = 74lvc1g125
D1-D5 = LED_2: LED, GREEN, 1206; Mfr Name: Dialight; Mfr P/N: 579-3311-407; Vendor Name: Digi-Key; Vendor P/N: 350-1345-1-ND
D7-D9 D?#4 = DIODE_2: manuf #: IN4148
GP4 GP6 GP13 GP20 GP21 = TEST_POINT
Q1 Q4 = PWRMOSFET_EP_DGS_0
Q5-Q7 = 2N1069_0
R111 R117 R124 R126 R138 R139 R142 R143 R181 R182 R214 R311 R312 R314 R321-R323 = R_1224: Agile number: RJX0365300; MFG: Panasonic - ECG; MFG_P/N: ERJ-3EKF4751V
R183 = R_1224: DESC: RES 100 Ohm 1/16W 1% SMT0402; UT_P/N: RJX0016100
U41 = 74HC1G07
U50 = LTD34D3
C11 = CAP_1: CAP, TANT, CASE_C, 100, 10%, 6.3V; Mfr Name: SANYO
C116 C123 C125 = C_1224: ALT_SYMBOLS: (SC0402,SC0402_BGA;B:SC0402,SC0402_BGA)
L15 L16 = INDUCTOR_0
L26 = INDUCTOR_2
R2-R5 R8 R9 R12 R16 = R_1224: RES 1Kohm, 1/10W, 5%, SMT 0603; Agile Number: RJX0054900; Manufacture: KOA; Part Number: RM73B1JT102J
R14 R221 R222 R244 R245 R248-R251 R357 R?#5 R?#6 = R_1224: RES, SMT, 0603,  5%; Mfr Name: ANY; Vendor Name: ANY
U2 = MAX708PCSA_3: IC +3 V, Voltage Monitoring uP Supervisory Circuits, SO8; Agile Number: IXX0727200; Manufacture: Analog Devices
U20 = TPS5401
U39 = OSC_HALF_0
U54 = XRP6668
XP1 = DIP12_01
U47 = MX25L1606E
C258-C265 C267 = CAPACITOR_NON-POL
C266 = CAPACITOR_POL_1
C268 = CAPACITOR_POL
J1 = J00-0061_PULSE
R355 = R_7
R356 = R_8
R358-R361 = 49R9-0805
R362 = R_2
R363 = R_4
R364 = R_5
R365 = R_3
R366 R367 = 0R-0603
R368 = R
R369 = R_1
R370 = R_6
U3 = RTL8169s_21

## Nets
1V0: C15.1 C20.1 C43.1 C45.1 C47.1 C48.1 C49.1 C50.1 C55.1 C56.1 C57.1 C58.1 C59.1 C60.1 C61.1 C62.1 C63.1 C64.1 C76.1 C77.1 C78.1 C79.1 C80.1 C81.1 C82.1 C83.1 C84.1 C91.1 C125.1 C126.1 C241.1 C242.1 C243.1 C244.1 L6.1 L16.2 R250.1 U31.F7(VDD10A_1) U31.F8(VDD10A_2) U31.F9(VDD10A_3) U31.F10(VDD10A_4) U31.G7(VDD10A_5) U31.G8(VDD10A_6) U31.G9(VDD10A_7) U31.G10(VDD10A_8) U31.H6(VDD10A_9) U31.H7(VDD10A_10) U31.H8(VDD10A_11) U31.H9(VDD10A_12) U31.H10(VDD10A_13) U31.J6(VDD10A_14) U31.J7(VDD10A_15) U31.J8(VDD10A_16) U31.J9(VDD10A_17) U31.J10(VDD10A_18) U31.K6(VDD10A_19) U31.K7(VDD10A_20) U31.K8(VDD10A_21)
1V0_SDS: C70.1 C71.1 C72.1 C73.1 C74.1 C75.1 C107.1 C108.1 C109.1 C110.1 L6.2 U31.M7(VDD10B_1) U31.M8(VDD10B_2) U31.N6(VDD10B_4) U31.N7(VDD10B_5) U31.N8(VDD10B_6) U31.N9(VDD10B_7) U31.N10(VDD10B_8)
2V5: C14.1 C19.1 C34.1 C35.1 C38.1 C39.1 C40.1 C41.1 C65.1 C66.1 C67.1 C68.1 C69.1 C85.1 C86.1 C87.1 C88.1 C89.1 C92.1 C93.1 C94.1 C95.1 C96.1 C106.1 C111.1 C112.1 C113.1 C114.1 C120.1 C123.1 C173.1 C174.1 C237.1 C238.1 C239.1 C240.1 C257.2 D3.2(CATHODE) L2.1 L15.2 R77.1 R100.1 R130.2 R215.2 R216.2 R219.2 R227.1 R228.2 R234.2 R248.1 U31.D7(VDD25A_1) U31.D8(VDD25A_2) U31.D11(VDD25A_3) U31.E4(VDD25A_4) U31.E12(VDD25A_5) U31.F4(VDD25A_6) U31.F12(VDD25C_1) U31.G2(VDD25A_7) U31.G4(VDD25A_8) U31.G11(VDD25B_1) U31.G12(VDD25C_2) U31.G14(VDD25A_9) U31.H4(VDD25C_3) U31.H11(VDD25B_2) U31.J4(VDD25A_10) U31.J11(VDD25B_3) U31.K4(VDD25A_11) U31.L11(VDD25A_12) U31.L12(VDD25A_13) U31.M4(VDD25A_14) U31.M5(VDD25A_15) U31.M12(VDD25A_16) U42.5(VCC) U52.5(VCC) U53.5(VCC)
3V3: C7.1 C16.1 C17.1 C18.1 C26.1 C27.1 C28.1 C30.1 C32.1 C33.1 C103.1 C124.1 C175.1 C191.1 C200.1 C203.1 C204.1 C205.1 C206.1 C207.1 C218.1 C219.1 C220.1 C230.1 C234.1 C235.1 C236.1 C253.2 C255.1 C?#2.2 JP17.1 L26.2 Q1.2(SOURCE) Q4.2(SOURCE) R2.2 R3.2 R4.2 R5.2 R9.2 R12.2 R14.2 R80.1 R89.1 R93.2 R94.2 R108.2 R117.2 R124.2 R126.2 R142.1 R143.1 R181.1 R214.1 R221.2 R222.2 R244.1 R288.2 R289.2 R305.1 R307.1 R355.2 R356.2 R357.1 U2.2(VCC) U3.15(DVDD33) U3.21(DVDD33) U31.D4(VDD33) U41.5(VCC) U47.8(VCC) U54.1(VIN1) U54.3(VIN2) U54.6(EN2) U54.8(EN1) U57.5(VCC)
5V: XP1.7(VDD)
12V: C3.1 C4.1 C5.1 C6.1 C11.1 C36.1 C104.1 C115.1 R1.2 U20.2(VIN) XP1.11(VCC) XP1.12(VCC)
DVDD12: C267.1 C268.1 U3.28(DVDD12) U3.40(PWOUT12D)
GND_EARTH: J1.8(P8) J1.15(P15) J1.16(P16) R367.2(R2)
GND_ETH: C258.1 C263.2 C264.2 R366.1(R1)
GND_POWER: R366.2(R2) R367.1(R1)
GND_SIGNAL: C3.2 C4.2 C5.2 C6.2 C7.2 C11.2 C12.2 C14.2 C15.2 C16.2 C17.2 C18.2 C19.2 C20.2 C26.2 C27.2 C28.2 C30.2 C32.2 C33.2 C34.2 C35.2 C36.2 C38.2 C39.2 C40.2 C41.2 C42.2 C43.2 C45.2 C46.2 C47.2 C48.2 C49.2 C50.2 C55.2 C56.2 C57.2 C58.2 C59.2 C60.2 C61.2 C62.2 C63.2 C64.2 C65.2 C66.2 C67.2 C68.2 C69.2 C70.2 C71.2 C72.2 C73.2 C74.2 C75.2 C76.2 C77.2 C78.2 C79.2 C80.2 C81.2 C82.2 C83.2 C84.2 C85.2 C86.2 C87.2 C88.2 C89.2 C90.2 C91.2 C92.2 C93.2 C94.2 C95.2 C96.2 C97.2 C98.2 C99.2 C103.2 C104.2 C106.2 C107.2 C108.2 C109.2 C110.2 C111.2 C112.2 C113.2 C114.2 C115.2 C116.2 C118.2 C120.2 C124.2 C126.2 C173.2 C174.2 C175.2 C183.2 C191.2 C198.1 C200.2 C203.2 C204.2 C205.2 C206.2 C207.2 C218.2 C219.2 C220.2 C230.2 C234.2 C235.2 C236.2 C237.2 C238.2 C239.2 C240.2 C241.2 C242.2 C243.2 C244.2 C250.1 C253.1 C254.1 C255.2 C256.1 C257.1 C259.2 C260.2 C261.2 C262.2 C265.2 C266.2 C267.2 C268.2 C?#2.1 C?#3.1 D2.1(ANODE) D4.1(ANODE) D5.1(ANODE) D?#4.1(A) JP17.2 Q5.2(E) Q6.2(E) Q7.2(E) R8.1 R79.2 R92.1 R101.1 R107.2 R110.1 R114.1 R125.1 R138.2 R139.2 R140.1 R182.2 R209.2 R211.2 R213.2 R217.2 R218.2 R225.1 R226.2 R235.2 R245.2 R249.2 R251.2 R278.1 R290.2 R291.2 R313.2 R365.1 R368.1 R369.2 R370.2 R?#5.2 U2.3(GND) U3.7(GND) U3.20(GND) U3.33(GND) U3.47(GND) U20.9(GND) U31.D5(GND1_1) U31.D6(GND1_2) U31.D9(GND1_3) U31.D10(GND1_4) U31.D12(GND1_5) U31.E5(GND1_6) U31.E6(GND1_7) U31.E7(GND1_8) U31.E8(GND1_9) U31.E9(GND1_10) U31.E10(GND1_11) U31.E11(GND1_12) U31.F5(GND1_13) U31.F6(GND1_14) U31.F11(GND1_15) U31.G1(GND1_16) U31.G5(GND1_17) U31.G6(GND1_18) U31.G15(GND1_19) U31.H5(GND1_20) U31.H12(GND1_21) U31.J5(GND1_22) U31.J12(GND1_23) U31.K5(GND1_24) U31.K9(GND1_25) U31.K10(GND1_26) U31.K11(GND1_27) U31.L5(GND1_28) U31.L6(GND1_29) U31.L7(GND1_30) U31.L8(GND1_31) U31.L9(GND1_32) U31.M6(GND1_33) U31.M10(GND1_34) U31.M11(THERMAL_GND) U31.P5(GND2_1) U31.P7(GND2_2) U31.P9(GND2_3) U31.R5(GND2_4) U31.R7(GND2_5) U31.R9(GND2_6) U39.2(GND) U41.3(GND) U42.3(GND) U47.4(GND) U50.2(RXVEE) U50.3(RXVEE) U50.6(RXVEE(1)) U50.12(TXVEE(7)) U50.16(TXVEE) U50.21(HL_GND) U50.22(HL_GND) U50.23(MS_GND) U50.24(MS_GND) U50.25(HL_GND) U50.26(HL_GND) U52.2(A) U52.3(GND) U53.2(A) U53.3(GND) U54.9(EPAD) U57.3(GND) XP1.9(VSS) XP1.10(VSS)
VCC_RX: C183.1 C250.2 Q4.3(DRAIN) R111.1 U50.7(RXVCC(2))
VCC_TX: C90.1 C198.2 Q1.3(DRAIN) R182.1 U50.11(TXVCC(6))
BOOT_M0: R226.1 R227.2 U31.B7(RMII_TXD_0_BOOT_M0)
BOOT_M1: R77.2 R79.1 U31.B8(RMII_TXD_1_BOOT_M1)
CPLL_REFCLK: R13.2 U31.R10(CPLL_REFCLK_P)
CPU_SEL: R218.1 U31.B12(PCM_FSYNC/CPU_SEL) U52.4(O)
CRS/RPTR: R364.2 R365.2 U3.36(CRS/RPTR)
DY_GASP: R7.2 U31.B3(GPIO_0)
ERX_SIGLOSS: GP20.1 R111.2 R138.1 U31.R12(ERX_SIGLOSS) U41.2(A) U50.8(SD(3))
ETX_nBURST: GP21.1 R117.1 R139.1 U31.R2(ETX_BURST) U50.13(TX_DIS(8))
EXT_CLK_SEL: R110.2 U31.N5(EXT_CLOCK_SEL)
GE_MODE: R209.1 R234.1 U31.M2(GTXD_3_GE_MODE)
GP1_P4_CTL: U31.D1(GPIO_1)
GP3_P3_CTL: R106.1 U31.H3(GPIO_3)
GP5_P2_CTL: R109.2 U31.K3(GPIO_5)
GP7_P1_CTL: R90.2 U31.M3(GPIO_7)
GP8_P1_RXD: R231.2 XP1.5(RXD)
GP9_P1_TXD: R230.2 XP1.8(TXD)
GP_INT: R362.1 U3.32(INTB) U31.E2(GPIO_12)
GP_WD_EN: R11.2 U31.C1(GPIO_10)
GP_WDI: R10.2 U31.F2(GPIO_11)
GREFCLK: R232.1 U3.42(CKXTAL1)
I2C_SCL: R81.1 R108.1 U50.17(SCL)
I2C_SDA: R82.1 R289.1 U50.18(SDA)
IC_RST: R290.1 U3.29(PHYRSTB) U31.E1(GPIO_2)
IMAGE_M0: R141.2 R225.2 U31.P14(CPD_DAT_EN_IN)
IMAGE_M1: R147.2 R217.1 R219.1 U42.1(A) U42.2(B)
INTCLK_SEL0: R213.1 U31.B10(PCM_TXD/INTCLK_SEL0) U53.4(O)
INTCLK_SEL1: R215.1 R317.2 U31.P1(GTXD_0_INTCLK_SEL1)
JTAG_MODE: R130.1 U31.N3(JTAG_MODE)
LASERON_SD: GP4.1 Q7.3(C) R126.1 U31.J3(GPIO_4)
LED0_AD0: U3.34(LED0/PHYAD0)
LED1_AD1: U3.35(LED1/PHYAD1)
LOS_LED: R121.1 U31.C2(GPIO_14)
MDC: R88.1 U3.30(MDC)
MDI0+: J1.1(P1) R359.2(R2) U3.1(MDI[0]+)
MDI0-: J1.2(P2) R358.2(R2) U3.2(MDI[0]-)
MDI1+: J1.3(P3) R360.2(R2) U3.4(MDI[1]+)
MDI1-: J1.6(P6) R361.2(R2) U3.5(MDI[1]-)
MDIO: R86.1 R363.1 U3.31(MDIO)
MEM_SEL: R216.1 U31.N1(GTXD_2_MEM_SEL)
PHY_AVDD33: C259.1 C260.1 R355.1 U3.6(AVDD33) U3.41(AVDD33)
PHY_VDD33: C261.1 C262.1 R356.1 R362.2 R363.2 R364.1 U3.37(DVDD33)
PLL_LOCK: U31.N4(PLL_LOCK) U52.1(OE) U53.1(OE)
PON_REG_LED: R123.1 U31.F1(GPIO_15)
PONRX_CTL: GP13.1 R323.1 U31.D2(GPIO_13)
PONTX_CTL: GP6.1 R322.1 U31.L3(GPIO_6)
RESETZ: R6.2 R85.1 R96.2
RGMII_GRXCTL: U31.K1(GRXCTL)
RGMII_GRXD_0: U3.14(RXD0) U31.L2(GRXD_0)
RGMII_GRXD_1: U3.16(RXD1) U31.K2(GRXD_1)
RGMII_GTXCLK: C98.1
RGMII_GTXCTL: R316.1 U3.27(TXEN)
RGMII_GTXD_0: R317.1
RGMII_GTXD_1: R318.1
RGMII_SW_INTR: R93.1 R135.1
RMII_TXD_0: U3.23(TXD0)
RMII_TXD_1: U3.24(TXD1)
RXN: U31.P8(ERX_N) U50.9(RXDN(4))
RXP: U31.R8(ERX_P) U50.10(RXDP(5))
SDM_SEL: R211.1 R235.1 R318.2 U31.N2(GTXD_1_SDM_SEL)
SPI_CLK: C99.1 R254.1 R288.1 U47.6(SCLK)
SPI_CS0: R94.1 U31.B1(SSP_CSN_0) U47.1(CS)
SPI_RXD: R270.1 U47.2(SDO)
SPI_TXD: R271.1 U47.5(SDI)
SYNC_CLKO: U31.R3(SYNC_CLKO)
TEST_MODE: R107.1 U31.L4(TEST_MODE)
TRSTN: R80.2 R278.2 U31.K12(TRSTN)
TXN: U31.P6(ETX_N) U50.15(TXDN(10))
TXP: U31.R6(ETX_P) U50.14(TXDP(9))
UART0_RXD: JP17.4 R89.2 R91.2
UART0_TXD: JP17.3 R95.2
N20285178: C46.1 R2.1 R16.2 U2.1(/MR)
N20285180: R3.1 R6.1 U2.7(/RST)
N20398921: D2.2(CATHODE) R14.1
N23827093: C12.1 R1.1 R8.2 U2.4(PFI)
N23843914: R4.1 R7.1 U2.5(PFO/)
N25264973: R95.1 U31.B4(UART_TXD)
N25264974: R91.1 U31.B5(UART_RXD)
N25507075: Q1.1(GATE) Q5.3(C) R181.2
N26196955: R135.2 U31.R1(GPHY_INTR)
N26204703: R316.2 U31.L1(GTXCTL)
N26311084: R271.2 U31.B2(SSP_TXD)
N26311085: R254.2 U31.A4(SSP_CLK)
N26311086: R270.2 U31.A3(SSP_RXD)
N26718244: R85.2 U31.P2(RESETN)
N27032257: R114.2 U31.P11(ATST_REXT_VTOI)
N27037651: R140.2 U31.R11(REXT_PMC)
N27049527: R228.1 U31.L10(THERMAL)
N27273676: C22.1 C31.1 R100.2 U31.P4(AB_PLL_VDDA)
N27276623: C22.2 C31.2 U31.R4(AB_PLL_VSSA)
N27654212: R142.2 R291.1 R311.1 R322.2
N27777033: D1.1(ANODE) U41.4(Y)
N27777044: D1.2(CATHODE) R307.2
N27918542: R143.2 R312.1 R313.1 R323.2
N27918606: Q4.1(GATE) Q6.3(C) R214.2
N28273239: R101.2 U31.P10(CPLL_REFCLK_N)
N28356058: R86.2 R305.2 U31.R13(MDIO)
N28360439: D3.1(ANODE) R125.2
N28387324: D4.2(CATHODE) R123.2
N28389261: D5.2(CATHODE) R121.2
N29545525: R92.2 U31.P3(EXT_CLOCK)
N29611791: D8.2(K) D9.1(A)
N29612336: D9.2(K) R321.1
N29612941: C97.1 C254.2 C256.2 D7.1(A) D8.1(A) R314.2
N29614342: D7.2(K) R124.1 R314.1 U50.20(TX_ON_IND)
N29908789: R148.2 U31.R14(CPD_CLK_FB_IN)
N30073790: C123.2 R248.2 R249.1 U54.7(VFB1)
N30074459: L15.1 U54.2(SW1)
N30077111: C125.2 R250.2 R251.1 U54.5(VFB2)
N30077141: L16.1 U54.4(SW2)
N30183416: R16.1 U57.4(Y)
N30187033: R9.1 R11.1 U57.2(B)
N30187361: R5.1 U2.8(/WDO) U57.1(A)
N30189338: R10.1 R12.1 U2.6(WDI)
N30240714: R230.1 U31.G3(GPIO_9)
N30241756: R231.1 U31.F3(GPIO_8)
N30246220: R232.2 U31.H1(GREFCLK)
N30257552: R13.1 U39.3(OUT)
N30257561: C42.1 L2.2 U39.1(N/C) U39.4(VDD)
N30481915: R221.1 U47.3(WP#)
N30482548: R222.1 U47.7(HOLD#)
N30503254: Q7.1(B) R321.2
N30503255: Q6.1(B) R312.2
N30503260: Q5.1(B) R311.2
N30503261: R183.1 U50.19(Tx_Fault)
N30565104: R147.1 U31.P15(IMAGE_M1_CPD_CLK_OUT)
N30616685: R141.1 U31.R15(IMAGE_M0_CPD_DAT_EN_OUT)
N30625689: R148.1 U42.4(Y)
N30673996: R81.2 U31.D3(BIWC)
N30673999: R82.2 U31.E3(BIWD)
N30678101: R90.1 XP1.2(EVENT)
N30678230: R106.2 XP1.3(STA)
N30678328: R96.1 XP1.4(~{RST})
N30678353: R109.1 XP1.6(~{SET})
N30679041: C265.1 C266.1 U3.48(PWOUT12A)
N30679141: R370.1 U3.46(RSET)
N30682003: R88.2 U31.P13(MDC)
N30688308: R357.2 U3.13(RXDV)
N30690281: R369.1 U3.39(RXER/FXEN)
N30690370: R368.2 U3.38(COL/SNI)
N30693751: C264.1 R360.1(R1) R361.1(R1)
N30693771: C258.2 R358.1(R1) R359.1(R1)
N30693773: C263.1 J1.4(P4) J1.5(P5)
N30705043: C?#1.1 U20.1(BOOST)
N30705048: C?#1.2 D?#4.2(K) L26.1 U20.10(PH)
N30705583: C?#3.2 U20.4(SS/TR)
N30705951: R?#5.1 U20.5(RT/CLK)
N30707690: R244.2 R245.1 U20.7(VSNS)
N30709900: C118.1 R?#6.1 U20.8(COMP)
N30709920: C116.1 R?#6.2

Not connected (* = marked no-connect by the designer): J1 7(P7)*; R183 2; U3 3(NC)* 8(NC)* 9(NC)* 10(NC)* 11(NC)* 12(NC)* 17(RXD2) 18(RXD3) 19(RXC) 22(TXC) 25(TXD2) 26(TXD3) 43(CKXTAL2) 44(NC)* 45(NC)*; U20 3(EN) 6(PR/RGD); U31 A1(SSP_CSN_2) A2(SSP_CSN_1) A5(PTP_PPS) A6(RMII_TXEN)* A7(RMII_RXDV)* A8(RMII_RXD_0)* A9(RMII_RXD_1)* A10(PCM_CLK)* A11(PCM_RXD)* A12(PCM_XOUT)* A13(LPB_ADDR_4)* A14(LPB_ADDR_9)* A15(LPB_ADDR_6)* B6(PTP_TOD) B9(RMII_REFCLK)* B11(PCM_XIN)* B13(LPB_ADDR_7)* B14(LPB_ADDR_10)* B15(LPB_ADDR_13)* C3(LPB_ADDR_0)* C4(LPB_ADDR_1)* C5(LPB_ADDR_2)* C6(LPB_ADDR_3)* C7(LPB_ADDR_5)* C8(LPB_ADDR_8)* C9(LPB_ADDR_11)* C10(LPB_ADDR_14)* C11(LPB_ADDR_17)* C12(SDRAM_DM0_LPB_ADDR_20)* C13(SDRAM_RAS_LPB_ADDR_23)* C14(LPB_ADDR_19)* C15(LPB_ADDR_16)* D13(SDRAM_CAS_LPB_ADDR_22)* D14(LPB_ADDR_15)* D15(LPB_ADDR_12)* E13(SDRAM_BA0_LPB_ADDR_24)* E14(SDRAM_DM1_LPB_ADDR_21)* E15(LPB_ADDR_18)* F13(SDRAM_BA1_LPB_ADDR_25)* F14(LPB_XDATA_3)* F15(LPB_XDATA_2)* G13(LPB_XDATA_13)* H2(GRXD_3) H13(LPB_XDATA_14)* H14(LPB_XDATA_10)* H15(LPB_XDATA_11)* J1(GRXCLK) J2(GRXD_2) J13(LPB_XDATA_15)* J14(LPB_XDATA_1)* J15(LPB_XDATA_12)* K13(LPB_WEN)* K14(LPB_XDATA_0)* K15(LPB_XDATA_7)* L13(SDRAM_CSN)* L14(LPB_XDATA_4)* L15(LPB_XDATA_8)* M1(GTXCLK) M9(NC#)* M13(FLASH_CSN)* M14(LPB_XDATA_5)* M15(LPB_XDATA_9)* N11(TDO) N12(TDI) N13(TMS) N14(LPB_XDATA_6)* N15(SDRAM_CKE_LPB_OEN)* P12(TCK); U41 1(NC)*; U50 1(NC2) 4(NC0) 5(NC1); XP1 1(NC)

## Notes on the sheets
sheet 1
- REVISION
- DESCRIPTION
- DATE
- 00
- Preliminary
- 05/22/11
- 01
- change lvc07 to lvc32
- 07/02/11
- CS8030 2-layer Main BOARD
- REV:01
- Table Of Contents
- Page 01        COVER PAGE
- Page 02        POWER RESET & CLOCK
- Page 03        ONU CS8030
- Page 04        PON PORT
- Page 05        FLASH
- Page 06        RTL SW
- Page 07        RJ45
- Page 08        RS485
- NOTES :
  1. Unless otherwise noted, all Resistor values are in OHMs,
     all Capacitor values are in FARADs, and all Inductor
     values are in HENRIES.
- This Document contains information  Proprietary to Cortina Systems
  Incorporated. Any use or disclosure, in whole or in part, of this
  information to any third or unauthorized party, for any purposes
  other than that for which it is provided is expressly prohibited
  except as authorized by Cortina Systems in writing. This document is
  protected under American, Canadian, and  foreign without the
  authorization of Cortina Systems Incorporated.
  copyright legislation which provides civil and criminal penalities
  for copying or disclosure.
  Cortina Systems Incorporated, 2001-2011
- Cortina Systems, Inc.
sheet 2
- RESET 200ms
  Hold Time
- Input
  Power
  Jack
  12V
- RESET
- PT7A7514WEX
  SP706SEN
  ADM706SAR
- POWER
- 25MHz
- Thick
- 2.5V@1A
- Thick
- Thick
- 1V@1A
- GSDR43-2R2
- PANEL LED
- GREEN
- POW
- GREEN
- PON
- RED
- LOS
- 1、删除VOIP功能的16M振荡器。
- 2、删除电源适配器插座和电源开关。
- 3、删除ADM706的手动复位SW5。
- Cortina Systems, Inc.
sheet 3
- Image download, 00: UART, 01: FLASH(default),10:RSV, 11:GE/FE
  BOOT mode.00: PFLASH 01: ROM, 10: SFLASH(default), 11: RSV
- CONFIGURATION
- Image1:0(PD/PU)  = 10(SPI_FLASH)/00(UART)
  Boot1:0(PU/PD)  = 10 (SPI_FLASH)/01(ROM)
  GTXD-3- GE_MODE(PD): 1 (RMII)
  GTXD-2- MEM_MAP_SEL(PD): 1 (INTERNAL SRAM)
  GTXD-1- SDM_SRAM_SEL(PD): 0(SIP SDRAM)
  GTXD-0- INT_CLK_SEL[1](PD):0
  PCM_TXD-INT_CLK_SEL[0](PD) :
  =10:ARM and AHB run at 125MHz
  CPU_SEL:0(internal cpu)
- L1
- L2
- L3
- L4
- PCB LAYOUT:
  loopback for timing adjust
  CPD_CLK_OUT -- CPD_CLK_FBIN
  same length with CLK
  CPD_DAT_OUT -- CPD_DATIN
  same length with DATA0:15
- 4 UART need only
- ARM9 Multi-ICE
  Connector
- AB_PLL_VDDA/VDDS
  the power and ground traces should be short,
  and run close and parallel as far as is
  possible, with large spacings to adjacent traces.
  must use Tan 22uF cap
- Pull low TRSTN normal work
  remove for ICE
- VCC
  GND
  TXD
  RXD
- Cortina Systems, Inc.
sheet 4
- OPTIONAL
- Laser always on detect
- ETX_DISABLE
  1: trans off
  0: trans on
  LOSS: "0"
- diff
- TX/RX AC COUPLING
  BUILDIN IN OPTICAL
  TRANSCIVER
  -3dBm TO -26dBm
- OPTIONAL
- LOSS: "0"
- LOS
- Cortina Systems, Inc.
sheet 5
- 1、删除8M容量的SPI FLASH芯片。
- SFLASH
  ALTERNATIVE
- 2、删除外扩的SDRAM芯片。
- 3、RS232芯片删除，直接TTL电平UART接出。
- Cortina Systems, Inc.
sheet 6
- RTL8201EL
- RJ45 ETHERNET CONNECTOR
- Cortina Systems, Inc.
sheet 8
- RS232_RS485
  external transceiver
- P1串口：与电能表的接口，国网型式要求双排插针。
- Cortina Systems, Inc.
